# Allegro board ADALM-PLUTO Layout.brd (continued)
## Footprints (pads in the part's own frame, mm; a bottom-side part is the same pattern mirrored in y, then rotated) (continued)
L0805
  rect 1.194x1.448 smd: 1(-0.85,0) 2(0.85,0)
L0805-4PH39
  rect 0.889x0.406 smd: 1(-0.845,-0.403) 2(0.845,-0.403) 3(0.845,0.403) 4(-0.845,0.403)
L0805-F
  rect 1.092x1.499 smd: 1(-1.046,0) 2(1.046,0)
L2020_A
  custom 0.425x0.425 smd: 1(-1.606,-1.501) 2(1.606,-1.501) 3(1.606,1.501) 4(-1.606,1.501)
LED0804
  rect 0.787x0.762 smd: A(1.1,0) C(-1.1,0)
LSMSQ79H41
  rect 1.041x2.21 smd: 1(-0.724,0) 2(0.724,0)
LSMSQ157H83
  rect 1.473x3.683 smd: 1(-1.232,0) 2(1.232,0)
MSOP12
  rect 0.406x1.397 smd: 1(-1.625,-2.2) 2(-0.975,-2.2) 3(-0.325,-2.2) 4(0.325,-2.2) 5(0.975,-2.2) 6(1.625,-2.2) 7(1.625,2.2) 8(0.975,2.2) 9(0.325,2.2) 10(-0.325,2.2) 11(-0.975,2.2) 12(-1.625,2.2)
QFN16_4X4_PAD2_1X2_1
  oval 0.356x1.041 smd: 1(-0.975,-1.9) 2(-0.325,-1.9) 3(0.325,-1.9) 4(0.975,-1.9) 9(0.975,1.9) 10(0.325,1.9) 11(-0.325,1.9) 12(-0.975,1.9)
  oval 1.041x0.356 smd: 5(1.9,-0.975) 6(1.9,-0.325) 7(1.9,0.325) 8(1.9,0.975) 13(-1.9,0.975) 14(-1.9,0.325) 15(-1.9,-0.325) 16(-1.9,-0.975)
  rect 2.108x2.108 smd: PAD(0,0)
QFN16_4X4_PAD2_5X2_5
  oval 0.356x0.991 smd: 1(-0.975,-1.974) 2(-0.325,-1.974) 3(0.325,-1.974) 4(0.975,-1.974) 9(0.975,1.974) 10(0.325,1.974) 11(-0.325,1.974) 12(-0.975,1.974)
  oval 0.991x0.356 smd: 5(1.974,-0.975) 6(1.974,-0.325) 7(1.974,0.325) 8(1.974,0.975) 13(-1.974,0.975) 14(-1.974,0.325) 15(-1.974,-0.325) 16(-1.974,-0.975)
  rect 2.489x2.489 smd: PAD(0,0)
QFN32_5X5_PAD3_1X3_1
  oval 0.305x0.889 smd: 1(-1.75,-2.45) 2(-1.25,-2.45) 3(-0.75,-2.45) 4(-0.25,-2.45) 5(0.25,-2.45) 6(0.75,-2.45) 7(1.25,-2.45) 8(1.75,-2.45) 17(1.75,2.45) 18(1.25,2.45) 19(0.75,2.45) 20(0.25,2.45) 21(-0.25,2.45) 22(-0.75,2.45) 23(-1.25,2.45) 24(-1.75,2.45)
  oval 0.889x0.305 smd: 9(2.45,-1.75) 10(2.45,-1.25) 11(2.45,-0.75) 12(2.45,-0.25) 13(2.45,0.25) 14(2.45,0.75) 15(2.45,1.25) 16(2.45,1.75) 25(-2.45,1.75) 26(-2.45,1.25) 27(-2.45,0.75) 28(-2.45,0.25) 29(-2.45,-0.25) 30(-2.45,-0.75) 31(-2.45,-1.25) 32(-2.45,-1.75)
  rect 3.099x3.099 smd: PAD(0,0)
QFN32_5X5_PAD3_3X3_3
  oval 0.305x0.889 smd: 1(-1.75,-2.45) 2(-1.25,-2.45) 3(-0.75,-2.45) 4(-0.25,-2.45) 5(0.25,-2.45) 6(0.75,-2.45) 7(1.25,-2.45) 8(1.75,-2.45) 17(1.75,2.45) 18(1.25,2.45) 19(0.75,2.45) 20(0.25,2.45) 21(-0.25,2.45) 22(-0.75,2.45) 23(-1.25,2.45) 24(-1.75,2.45)
  oval 0.889x0.305 smd: 9(2.45,-1.75) 10(2.45,-1.25) 11(2.45,-0.75) 12(2.45,-0.25) 13(2.45,0.25) 14(2.45,0.75) 15(2.45,1.25) 16(2.45,1.75) 25(-2.45,1.75) 26(-2.45,1.25) 27(-2.45,0.75) 28(-2.45,0.25) 29(-2.45,-0.25) 30(-2.45,-0.75) 31(-2.45,-1.25) 32(-2.45,-1.75)
  rect 3.302x3.302 smd: PAD(0,0)
R0201
  rect 0.305x0.406 smd: 1(-0.318,0) 2(0.318,0)
R0402
  rect 0.61x0.61 smd: 1(-0.495,0) 2(0.495,0)
R0603
  rect 0.889x0.813 smd: 1(-0.737,0) 2(0.737,0)
R0603#2
  rect 0.711x0.914 smd: 1(-0.6,0) 2(0.6,0)
R0603H18
  rect 0.94x0.991 smd: 1(-0.787,0) 2(0.787,0)
R0805
  rect 0.838x1.295 smd: 1(-0.85,0) 2(0.85,0)
SON10_2X2_PAD1_5X0_9
  oval 0.203x0.762 smd: 1(-0.8,-1) 2(-0.4,-1) 3(0,-1) 4(0.4,-1) 5(0.8,-1) 6(0.8,1) 7(0.4,1) 8(0,1) 9(-0.4,1) 10(-0.8,1)
  rect 1.499x0.889 smd: PAD(0,0)
SOT23
  rect 1.016x1.397 smd: 1(-0.94,-1.118) 2(0.94,-1.118) 3(0,1.118)
SOT353
  rect 0.33x0.94 smd: 1(-0.65,-0.89) 2(0,-0.89) 3(0.65,-0.89) 4(0.65,0.89) 5(-0.65,0.89)
SOT-563
  rect 0.305x0.508 smd: 1(-0.508,-0.699) 2(0,-0.699) 3(0.508,-0.699) 4(0.508,0.699) 5(0,0.699) 6(-0.508,0.699)
SWSML140W138H55
  round 0.889 hole 0.711 unplated: (-0.9,0) (0.9,0)
  rect 1.041x1.397 smd: 1(-0.721,-1.799) 2(-0.721,1.799) 3(0.721,-1.799) 4(0.721,1.799)
  rect 0.508x1.092 smd: 5(-1.704,0)
TBGA24
  round 0.33 smd: A2(-2,-1) A3(-2,0) A4(-2,1) A5(-2,2) B1(-1,-2) B2(-1,-1) B3(-1,0) B4(-1,1) B5(-1,2) C1(0,-2) C2(0,-1) C3(0,0) C4(0,1) C5(0,2) D1(1,-2) D2(1,-1) D3(1,0) D4(1,1) D5(1,2) E1(2,-2) E2(2,-1) E3(2,0) E4(2,1) E5(2,2)
TPC75D45
  round 1.905 hole 1.143: 1(0,0)
TPSMC40
  round 1.016 hole 0.508: 1(0,0)
TSML150W160H160
  rect 0.762x1.651 smd: 1(-1.27,1.587) 2(0,1.587) 3(1.27,1.587) 4(1.27,-1.587) 5(0,-1.587) 6(-1.27,-1.587)
unnamed
  round 0.889 hole 0.635 unplated: (0,0)
unnamed#3
  round 1.651 hole 1.143: 1(0,0)
WLCSP4-2
  round 0.254 smd: A1(-0.25,-0.25) A2(-0.25,0.25) B1(0.25,-0.25) B2(0.25,0.25)
YSML98W79H35
  rect 1.092x0.991 smd: 1(-0.921,-0.72) 2(0.921,-0.72) 3(0.921,0.72) 4(-0.921,0.72)
YSML126W98H47
  rect 1.397x1.194 smd: 1(-1.2,-0.95) 2(1.2,-0.95) 3(1.2,0.95) 4(-1.2,0.95)

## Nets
1V8: C1.1 C10.1 C22.1 C25.1 C46.1 C48.1 C49.1 C50.1 C51.1 C52.1 C53.1 C65.1 C67.1 C69.1 C76.1 C77.1 C78.1 C82.1 C83.1 C90.1 C103.1 C104.1 C105.1 C106.1 C107.1 C108.1 C109.1 C110.1 C111.1 C112.1 C113.1 C114.1 C115.1 C116.1 C117.1 C118.1 C119.1 C120.1 C140.1 C149.1 C150.1 C152.1 C153.1 C154.1 C158.1 C159.1 C160.1 C161.1 C162.1 C163.2(N2) C168.1 C174.1 C186.1 C190.1 E1.1 E4.1 E5.1 L5.2(N2) P1.10(N5) R8.1 R11.1 R13.1 R14.1 R44.1 R45.1 R46.2(N2) R47.2(N2) R50.2(N2) R57.1 R64.2(N2) R68.1 R74.1 R76.1 R83.1 R84.2(N2) R94.1 R97.1 R107.1 R122.2(N2) U1.1 U1.2 U1.3 U1.15 U1.16 U4.A6 U4.B13 U4.C10 U4.D7 U4.E14 U4.F11 U4.G4 U4.H4 U4.H9 U4.H15 U4.J4 U4.J6 U4.J8 U4.J12 U4.K8 U4.K9 U4.L6 U4.M13 U4.N10 U4.P7 U4.R14 U7.1 U7.2 U7.3 U7.15 U7.16 U9.1(VCCIO) U10.5 U13.B4 U15.8 U15.11 U15.14 U15.28 U15.30 U15.32 UNK1V8.1 UNK1V8#2.1 Y1.4(VDD) Y2.4(VDD)
1V35: C54.1 C55.1 C56.1 C57.1 C58.1 C59.1 C60.1 C61.1 C86.1 C87.1 C88.1 C89.1 C91.1 C92.1 C94.1 C95.1 C96.1 C97.1 C100.1 C145.1 C148.1 C151.1 L2.2(N2) R41.2(N2) R62.1 U2.A1 U2.A8 U2.B2 U2.C1 U2.C9 U2.D2 U2.D9 U2.E9 U2.F1 U2.G7 U2.H2 U2.H9 U2.K2 U2.K8 U2.N1 U2.N9 U2.R1 U2.R9 U4.B3 U4.E4 U4.F1 U4.J2 U4.M3 U4.R4 U14.1 UNK1V35.1
GND: C1.2(N2) C2.2(N2) C3.2(N2) C4.2(N2) C5.2(N2) C6.2(N2) C7.1 C8.2(N2) C9.2(N2) C10.2(N2) C11.2(N2) C12.2(N2) C13.2(N2) C14.2(N2) C15.2(N2) C16.2(N2) C17.2(N2) C18.2(N2) C19.2(N2) C20.2(N2) C21.2(N2) C22.2(N2) C23.2(N2) C24.2(N2) C25.2(N2) C26.2(N2) C27.2(N2) C28.2(N2) C29.2(N2) C30.2(N2) C31.2(N2) C32.2(N2) C33.2(N2) C34.2(N2) C35.2(N2) C36.2(N2) C37.2(N2) C38.2(N2) C39.2(N2) C40.2(N2) C41.2(N2) C42.2(N2) C43.2(N2) C44.2(N2) C45.2(N2) C46.2(N2) C47.2(N2) C48.2(N2) C49.2(N2) C50.2(N2) C51.2(N2) C52.2(N2) C53.2(N2) C54.2(N2) C55.2(N2) C56.2(N2) C57.2(N2) C58.2(N2) C59.2(N2) C60.2(N2) C61.2(N2) C62.1 C63.1 C64.2(N2) C65.2(N2) C66.2(N2) C67.2(N2) C68.2(N2) C69.2(N2) C70.2(N2) C71.2(N2) C72.2(N2) C73.2(N2) C74.2(N2) C75.2(N2) C76.2(N2) C77.2(N2) C78.2(N2) C79.2(N2) C80.2(N2) C81.2(N2) C82.2(N2) C83.2(N2) C84.2(N2) C85.2(N2) C86.2(N2) C87.2(N2) C88.2(N2) C89.2(N2) C90.2(N2) C91.2(N2) C92.2(N2) C94.2(N2) C95.2(N2) C96.2(N2) C97.2(N2) C99.1 C100.2(N2) C101.2(N2) C102.2(N2) C103.2(N2) C104.2(N2) C105.2(N2) C106.2(N2) C107.2(N2) C108.2(N2) C109.2(N2) C110.2(N2) C111.2(N2) C112.2(N2) C113.2(N2) C114.2(N2) C115.2(N2) C116.2(N2) C117.2(N2) C118.2(N2) C119.2(N2) C120.2(N2) C121.2(N2) C122.2(N2) C123.2(N2) C124.2(N2) C125.1 C126.1 C127.2(N2) C128.2(N2) C129.1 C135.2(N2) C136.2(N2) C137.2(N2) C138.2(N2) C139.1 C140.2(N2) C141.2(N2) C142.1 C143.1 C145.2(N2) C146.2(N2) C147.1 C148.2(N2) C149.2(N2) C150.2(N2) C151.2(N2) C152.2(N2) C153.2(N2) C154.2(N2) C155.2(N2) C158.2(N2) C159.2(N2) C160.2(N2) C161.2(N2) C162.2(N2) C163.1 C164.2(N2) C165.2(N2) C166.1 C167.2(N2) C168.2(N2) C169.2(N2) C170.2(N2) C171.2(N2) C172.2(N2) C173.2(N2) C174.2(N2) C177.1 C178.2(N2) C180.2(N2) C182.2(N2) C183.2(N2) C184.2(N2) C185.2(N2) C186.2(N2) C187.2(N2) C188.2(N2) C189.2(N2) C190.2(N2) C191.2(N2) C192.2(N2) C193.1 C194.1 C195.2(N2) C196.1 C197.1 C198.2(N2) C199.2(N2) C200.2(N2) C201.2(N2) C202.2(N2) C203.2(N2) C205.2(N2) C206.2(N2) C207.1 C208.2(N2) C209.2(N2) C210.2(N2) C211.2(N2) C212.2(N2) C213.2(N2) C215.2(N2) CLK_IN.2 CLK_IN.3(SH2) CLK_OUT.2 CLK_OUT.3(SH2) D1.2 D3.1 D4.1 D7.1 D8.1 D9.1 D10.1 E6.1 E10.1 GND.1 GND#2.1 GND#3.1 GND#4.1 L10.3 P1.7 P1.9 P2.5 Q1.2(S) Q2.2(S) Q3.2(S) Q4.2(S) R2.1 R3.1 R9.2(N2) R15.2(N2) R40.2(N2) R42.2(N2) R49.1 R53.1 R54.2(N2) R55.2(N2) R61.1 R63.2(N2) R65.1 R66.1 R69.1 R72.2(N2) R73.2(N2) R75.2(N2) R77.2(N2) R78.1 R90.2(N2) R91.2(N2) R92.2(N2) R93.2(N2) R99.2(N2) R103.2(N2) R104.1 R116.2(N2) R119.2(N2) R120.2(N2) R121.2(N2) R165.2(N2) RX1A.2 RX1A.3 RX1A.4 RX1A.5(SH4) RX2A.2 RX2A.3(SH2) S1.3 S1.4 T1.1 T1.2 T1.5 T2.1 T2.2 T2.5 T3.1 T3.2 T3.5 T5.1 T5.2 T5.5 TX1A.2 TX1A.3 TX1A.4 TX1A.5(SH4) TX2A.2 TX2A.3(SH2) U1.6 U1.PAD U2.A9 U2.B1 U2.B3 U2.B9 U2.D1 U2.D8 U2.E1 U2.E2 U2.E8 U2.F9 U2.G1 U2.G8 U2.G9 U2.J2 U2.J8 U2.M1 U2.M9 U2.P1 U2.P9 U2.T1 U2.T9 U3.5 U3.6 U3.7 U3.8 U3.PAD U4.A1 U4.A11 U4.B8 U4.C5 U4.C15 U4.D2 U4.D12 U4.E5 U4.E7 U4.E8 U4.E9 U4.F10 U4.G3 U4.G5 U4.G13 U4.H6 U4.H8 U4.H10 U4.J5 U4.J9 U4.K4 U4.K7 U4.K10 U4.K14 U4.L1 U4.L5 U4.L11 U4.M8 U4.N5 U4.N15 U4.P2 U4.P12 U4.R9 U5.A4 U5.A5 U5.A6 U5.A12 U5.B1 U5.B2 U5.B12 U5.C1 U5.C2 U5.C4 U5.C7 U5.C8 U5.C9 U5.C10 U5.C11 U5.C12 U5.D1 U5.D12 U5.E1 U5.F1 U5.F3 U5.F7 U5.F9 U5.F11 U5.G1 U5.G10 U5.G12 U5.H1 U5.H2 U5.H3 U5.H5 U5.H6 U5.H7 U5.H9 U5.H10 U5.J1 U5.J2 U5.K1 U5.K2 U5.K12 U5.L1 U5.L2 U5.L3 U5.L7 U5.L8 U5.L9 U5.L10 U5.L11 U5.L12 U5.M4 U5.M5 U5.M6 U6.1 U6.19 U6.20 U6.21 U6.22 U6.PAD U7.6 U7.PAD U8.PAD U9.3 U9.13 U9.PAD U10.3 U11.3 U11.PAD U12.3 U12.PAD U13.B3 U14.4 U14.8 U14.PAD U15.PAD U16.B2 U17.1 U17.5 U17.8 Y1.2 Y2.2 Y3.2
PGND: C181.1 C214.2(N2) D2.2 E10.2(N2) L10.4(N4) P3.5 R58.2(N2)
VCCPINT: C17.1 C19.1 C20.1 C21.1 C64.1 C66.1 C68.1 C70.1 C71.1 C72.1 C73.1 C74.1 C75.1 L4.2(N2) R7.2(N2) U4.E10 U4.F9 U4.G6 U4.G10 U4.H5 U4.J10 U4.K5 U4.L10 UNK1P0V.1
VCCPLL: C85.1 C178.1 E1.2(N2) U4.F5(VCCPLL)
VDD33_USB: C165.1 U15.20
VDD_INTERFACE: C32.1 C33.1 C38.1 C43.1 C44.1 C45.1 E4.2(N2) U5.H12
VDDA1P1_RX_VCO: C125.2(N2) R51.2(N2) U5.G2 U5.G3
VIN: C8.1 C9.1 C11.1 C62.2(N2) C123.1 C135.1 C136.1 C137.1 C138.1 C164.1 C169.1 C184.1 C185.1 C188.1 C215.1 DS1.A(P) DS2.A(P) E2.1 E7.1 R1.2(N2) R6.1 R56.1 R59.2(N2) R221.1 R222.1 U3.12 U3.13 U6.14 U6.15 U6.16(VIN6) U6.25 U6.26 U6.27 U6.28 U8.9 U8.10 U8.15 U8.16 U9.10 U14.10 U15.21
VIN_5V_USB_DATA: C183.1 C210.1 E3.1 F1.2(N2) R88.1 U8.7 U8.8
VIN_5V_USB_POWER: C182.1 C209.1 C212.1 E9.1 R70.1 R80.1 U8.1 U8.2 U16.A1
1P3_SUPPLY_A: C14.1 C15.1 C16.1 C18.1 C23.1 C24.1 C28.1 C29.1 C34.1 C35.1 C39.1 C40.1 U5.B9 U5.B10 U5.E2 U5.F2 U5.J3 U5.K3 U7.9 U7.10 U7.11 U7.12 U7.13 U7.14(VOUT5) UNK1P3V_A.1
1P3_SUPPLY_B: C3.1 C4.1 C5.1 C6.1 C26.1 C27.1 C30.1 C31.1 C36.1 C37.1 C41.1 C42.1 C129.2(N2) C155.1 C166.2(N2) C167.1 C191.1 C192.1 C193.2(N2) C194.2(N2) L1.1 L7.1 L8.1 L9.1 U1.9 U1.10 U1.11 U1.12 U1.13 U1.14(VOUT5) U5.A9 U5.A10 U5.D2 U5.D3 U5.E3 U5.F12 U5.K4 U5.M9 U5.M10 UNK1P3V_B.1
1P8V_CLK: C121.1 C122.1 C170.1 R101.1 U12.1(VOUT) UNK1P8V_CLK.1 Y3.4(VDD)
3P3V: C198.1 C199.1 C203.1 E8.1 U5.B8 U11.1(VOUT) VDD_GPO.1(N1)
3P3V_CLK: C200.1 C201.1 C202.1 E8.2(N2) R85.1 U17.2 U17.6 U17.11(VDD)
AD9363_AUXADC: ADC.1(N1) C207.2(N2) U5.L5
AD9363_AUXDAC1: C206.1 DAC1.1(N1) R5.1 U5.B3
AD9363_AUXDAC2: C208.1 DAC2.1(N1) U5.C3
AD9363_GPO_0: GPO0.1(N1) U5.B7
AD9363_GPO_1: GPO1.1(N1) U5.B6
AD9363_GPO_2: GPO2.1(N1) U5.B5
AD9363_GPO_3: GPO3.1(N1) U5.B4
ADP2114_VIN: C141.1 R56.2(N2) U6.4 U6.8 U6.10 U6.31
CLK_SOURCE_SEL: Q2.1 Q3.1 R102.1 R103.1
COMP_1P8V: C142.2(N2) R60.1 U6.2
COMP_1P35V: C143.2(N2) C144.1 U6.7
CTRL_IN0: U4.F13 U5.C5
CTRL_IN1: U4.F14 U5.C6
CTRL_IN2: U4.G15 U5.D6
CTRL_IN3: U4.F15 U5.D5
DDR3_A0: R16.1 U2.N3 U4.P1
DDR3_A1: R22.1 U2.P7 U4.N1
DDR3_A2: R17.1 U2.P3 U4.M1
DDR3_A3: R23.1 U2.N2 U4.M4
DDR3_A4: R18.1 U2.P8 U4.P3
DDR3_A5: R24.1 U2.P2 U4.P4
DDR3_A6: R19.1 U2.R8 U4.P5
DDR3_A7: R25.1 U2.R2 U4.M5
DDR3_A8: R20.1 U2.T8 U4.P6
DDR3_A9: R26.1 U2.R3 U4.N4
DDR3_A10: R21.1 U2.L7 U4.J1
DDR3_A11: R27.1 U2.R7 U4.L2
DDR3_A12: R28.1 U2.N7 U4.M2
DDR3_A13: R34.1 U2.T3 U4.K2
DDR3_A14: R29.1 U2.T7 U4.K1
DDR3_BA0: R35.1 U2.M2 U4.M6
DDR3_BA1: R30.1 U2.N8 U4.R1
DDR3_BA2: R36.1 U2.M3 U4.N6
DDR3_CAS#: R32.1 U2.K3 U4.R5
DDR3_CK_N: R142.2(N2) U2.K7 U4.N2
DDR3_CK_P: R142.1 U2.J7 U4.N3
DDR3_CKE: R38.1 U2.K9 U4.L3
DDR3_CS#: R39.1 U2.L2 U4.R2
DDR3_DM0: U2.E7 U4.B1
DDR3_DM1: U2.D3 U4.D3
DDR3_DQ0: U2.E3 U4.D4
DDR3_DQ1: U2.F7 U4.A2
DDR3_DQ2: U2.F2 U4.C4
DDR3_DQ3: U2.F8 U4.C1
DDR3_DQ4: U2.H3 U4.B4
DDR3_DQ5: U2.H8 U4.A4
DDR3_DQ6: U2.G2 U4.C3
DDR3_DQ7: U2.H7 U4.A3
DDR3_DQ8: U2.D7 U4.E1
DDR3_DQ9: U2.C3 U4.D1
DDR3_DQ10: U2.C8 U4.E2
DDR3_DQ11: U2.C2 U4.E3
DDR3_DQ12: U2.A7 U4.F3
DDR3_DQ13: U2.A2 U4.G1
DDR3_DQ14: U2.B8 U4.H1
DDR3_DQ15: U2.A3 U4.H2
DDR3_DQS0_N: U2.G3 U4.B2
DDR3_DQS0_P: U2.F3 U4.C2
DDR3_DQS1_N: U2.B7 U4.F2
DDR3_DQS1_P: U2.C7 U4.G2
DDR3_ODT: R33.1 U2.K1 U4.K3
DDR3_RAS#: R37.1 U2.J3 U4.R6
DDR3_RST#: R42.1 U2.T2 U4.L4
DDR3_WE#: R31.1 U2.L3 U4.R3
EN_DAT_USB: R71.2(N2) R72.1 U8.6
EN_POW_USB: R70.2(N2) R71.1 U8.3
FB0: R2.2(N2) R4.1 U3.4
FB_1P8V: R64.1 R65.2(N2) U6.32
FB_1P35V: R62.2(N2) R63.1 U6.9
IO_02_34_AD9361_CLKOUT: AD9361_CLKOUT.1(N1) U4.P8 U5.J6
IO_02_34_AD9361_RST: U4.P9 U5.K5
IO_L01_34_FB_CLK: U4.P10 U5.F10
IO_L01_34_RX_D0: U4.H14 U5.K11
IO_L01_34_RX_D1: U4.J13 U5.J12
IO_L02_34_RX_D2: U4.G14 U5.K10
IO_L02_34_RX_D3: U4.H13 U5.J11
IO_L03_34_RX_D4: U4.G12 U5.K9
IO_L03_34_RX_D5: U4.H12 U5.J10
IO_L04_34_RX_D6: U4.G11 U5.K8
IO_L04_34_RX_D7: U4.J14 U5.J9
IO_L05_34_RX_D8: U4.J15 U5.K7
IO_L05_34_RX_D9: U4.K15 U5.J8
IO_L06_34_RX_D10: U4.H11 U5.J7
IO_L06_34_RX_D11: U4.J11 U5.H8
IO_L07_34_RX_FRAME: U4.N13 U5.G8
IO_L08_34_CTRL_OUT0: U4.L15 U5.D4
IO_L08_34_CTRL_OUT1: U4.M15 U5.E4
IO_L09_34_TX_FRAME: U4.L14 U5.G9
IO_L10_34_EN_AGC: U4.L13 U5.G5
IO_L11_34_ENABLE: U4.K12 U5.G6
IO_L11_34_TXNRX: U4.K11 U5.H4
IO_L12_MRCC_34_DATA_CLK: U4.L12 U5.G11
IO_L13_34_CTRL_OUT2: U4.N11 U5.E5
IO_L13_34_CTRL_OUT3: U4.N12 U5.E6
IO_L15_34_TX_D0: U4.P15 U5.E12
IO_L15_34_TX_D1: U4.R13 U5.D11
IO_L16_34_TX_D2: U4.R15 U5.E11
IO_L16_34_TX_D3: U4.P11 U5.D10
IO_L17_34_TX_D4: U4.R11 U5.E10
IO_L17_34_TX_D5: U4.R12 U5.D9
IO_L18_34_TX_D6: U4.P14 U5.E9
IO_L18_34_TX_D7: U4.P13 U5.D8
IO_L19_34_TX_D8: U4.N9 U5.E8
IO_L19_34_TX_D9: U4.M9 U5.D7
IO_L20_34_TX_D10: U4.R8 U5.F8
IO_L20_34_TX_D11: U4.R7 U5.E7
IO_L21_34_CTRL_OUT4: U4.M10 U5.F6
IO_L21_34_CTRL_OUT5: U4.M11 U5.F5
IO_L22_34_CTRL_OUT6: U4.N7 U5.F4
IO_L22_34_CTRL_OUT7: U4.N8 U5.G4
IO_L23_35_SPI_CLK: U4.E11 U5.J5
IO_L23_35_SPI_ENB: U4.E12 U5.K6
IO_L24_35_SPI_DI: U4.E13 U5.J4
IO_L24_35_SPI_DO: U4.F12 U5.L6
JTAG_TCK: P1.4 TCK.1(N1) U4.G9
JTAG_TDI: P1.8 TDI.1(N1) U4.L7
JTAG_TDO: P1.6 TDO.1(N1) U4.L8
JTAG_TMS: P1.2 TMS.1(N1) U4.L9
PG_1P0V: R6.2(N2) U3.16
PG_1P3V: C47.1 PG_1P3V.1(N1) R13.2(N2) R15.1 U1.5 U4.C9 U7.5 U11.4 U12.4
PG_1P8V: R59.1 U6.13 U6.29
PG_1P35V: R50.1 U1.4 U6.12 U7.4
PL_GPIO0: L10P.1(N1) U4.K13
PL_GPIO1: L12N.1(N1) U4.M12
PL_GPIO2: L24N.1(N1) U4.R10
PL_GPIO3: L7N.1(N1) R97.2(N2) U4.N14
PL_GPIO4: L9N.1(N1) R68.2(N2) U4.M14
PS-SRST#: R74.2(N2) U4.B11 U13.A4
PS_GPIO0: MIO0.1(N1) U4.D8
PS_GPIO1: MIO10.1(N1) U4.B10
PS_GPIO2: MIO11.1(N1) U4.D6
PS_GPIO3: MIO09.1(N1) U4.B5
PS_GPIO4: MIO53.1(N1) U4.C13
PS_GPIO5: MIO49.1(N1) U4.D13
PS_GPIO6: MIO48.1(N1) R102.2(N2) U4.B12
PS_MIO01_500_QSPI0_SS_B: R14.2(N2) U4.A5 U13.C2
PS_MIO02_500_QSPI0_IO0: R120.1 U4.A8 U13.D3
PS_MIO03_500_QSPI0_IO1: R119.1 U4.A7 U13.D2
PS_MIO04_500_QSPI0_IO2: R121.1 U4.C8 U13.C4(W#DQ2)
PS_MIO05_500_QSPI0_IO3: JTAG_BOOT.1(N1) P1.5 R122.1 U4.A9 U13.D4
PS_MIO06_500_QSPI0_SCLK: R116.1 U4.A10 U13.B2
PS_MIO07_500_USB_RESET_B: R76.2(N2) U4.A12 U15.27
PS_MIO28_501_USB0_D4: U4.A15 U15.7
PS_MIO29_501_USB0_DIR: U4.D11 U15.31
PS_MIO30_501_USB0_STP: U4.B15 U15.29
PS_MIO31_501_USB0_NXT: U4.C12 U15.2
PS_MIO32_501_USB0_D0: U4.E15 U15.3
PS_MIO33_501_USB0_D1: U4.C11 U15.4
PS_MIO34_501_USB0_D2: U4.D15 U15.5
PS_MIO35_501_USB0_D3: U4.A14 U15.6
PS_MIO36_501_USB0_CLK: U4.B14 U15.1
PS_MIO37_501_USB0_D5: U4.C14 U15.9
PS_MIO38_501_USB0_D6: U4.A13 U15.10
PS_MIO39_501_USB0_D7: U4.D14 U15.13
PWR_CLK: R89.2(N2) R90.1 U3.1
RX1A_N: C133.2(N2) U5.M2
RX1A_P: C134.2(N2) U5.M1
RX2A_N: C175.2(N2) R69.2(N2) U5.A1
RX2A_P: C176.2(N2) R104.2(N2) U5.A2
SYNC: L4.1 U3.9 U3.10 U3.11
TX1A_N: C131.1 L8.2(N2) U5.M8
TX1A_P: C132.1 L9.2(N2) U5.M7
TX2A_N: C130.1 L1.2(N2) U5.A7
TX2A_P: C156.1 L7.2(N2) U5.A8
TX_VCO_1P1V_SUPPLY: C128.1 R52.1 U5.A11 U5.B11
UART_RX: P1.1 R95.2(N2) RX.1(N1) U4.C6
UART_TX: P1.3 TX.1(N1) U4.B7 U9.2
UNNAMED_2_ADM7160V2_I254_VIN: C173.1 E2.2(N2) U12.6
UNNAMED_2_ADM7160V2_I348_VIN: C195.1 E7.2(N2) U11.6
UNNAMED_2_ADP1754_I93_SS: C2.1 U1.7
UNNAMED_2_ADP1754_I233_SS: C12.1 U7.7
UNNAMED_2_ADP2164_I29_EN: C13.1 R1.1 U3.3 U3.14(VIN) U3.15
UNNAMED_2_ADP2164_I29_RT: R3.2(N2) U3.2
UNNAMED_2_RES_I251_N2: R4.2(N2) R7.1
UNNAMED_3_ICXC7Z010_I16_PSCLK50: R12.2(N2) U4.C7
UNNAMED_3_ICXC7Z010_I16_PSMIO75: R83.2(N2) U4.D9
UNNAMED_3_ICXC7Z010_I16_PSMIO85: R84.1 U4.B6
UNNAMED_3_RES_I2_N1: R8.2(N2) R9.1 Y2.1
UNNAMED_3_RES_I48_N1: R12.1 Y2.3
UNNAMED_4_ICMT41K256M16_I98_ZQ: R165.1 U2.L8(ZQ)
UNNAMED_4_ICTPS51206_I44_S3: R222.2(N2) U14.7
UNNAMED_4_ICTPS51206_I44_S5: R221.2(N2) U14.9
UNNAMED_4_ICTPS51206_I44_VLDOIN: R44.2(N2) U14.2
UNNAMED_4_ICTPS51206_I44_VTTSNS: C80.1 R43.2(N2) U14.5(VTTSNS)
UNNAMED_4_ICXC7Z010_I26_PSDDR_1: R40.1 U4.H3
UNNAMED_4_ICXC7Z010_I26_PSDDRVR: R41.1 U4.J3
UNNAMED_5_CAP_I83_N1: C93.1 C98.1 E5.2(N2) U4.F7
UNNAMED_5_CAP_I83_N2: C93.2(N2) C98.2(N2) E6.2(N2) U4.F6 U4.F8 U4.G8 U4.H7 U4.J7
UNNAMED_5_DIOLED_I62_N: DS2.C R87.1
UNNAMED_5_DIOLED_I91_N: DS1.C R48.1
UNNAMED_5_ICXC7Z010_I93_DONE0: Q1.1 U4.M7
UNNAMED_5_ICXC7Z010_I93_INITB0: R47.1 U4.D5
UNNAMED_5_ICXC7Z010_I93_PROGRAM: R46.1 U4.K6
UNNAMED_5_ICXC7Z010_I93_VCCBATT: R45.2(N2) U4.E6
UNNAMED_5_ICXC7Z010_I93_VP0: R11.2(N2) R66.2(N2) R91.1 U4.G7
UNNAMED_5_RES_I63_N2: Q4.3 R87.2(N2)
UNNAMED_5_RES_I90_N2: Q1.3 R48.2(N2)
UNNAMED_7_AD9363_I87_RBIAS: R49.2(N2) U5.L4
UNNAMED_7_AD9363_I87_XTALN: C124.1 C157.2(N2) C204.2(N2) U5.M12(XTALN)
UNNAMED_7_CAP_I14_N1: C157.1 R86.2(N2) R99.1
UNNAMED_7_CAP_I22_N2: C126.2(N2) R51.1
UNNAMED_7_CAP_I25_N1: C127.1 R52.2(N2)
UNNAMED_7_CAP_I57_N2: C132.2(N2) T5.4
UNNAMED_7_CAP_I58_N2: C131.2(N2) T5.6(SEC_DOT)
UNNAMED_7_CAP_I85_N1: C134.1 T1.4
UNNAMED_7_CAP_I86_N1: C133.1 T1.6(SEC_DOT)
UNNAMED_7_CAP_I92_N1: C179.1 CLK_IN.1 D7.2(N2)
UNNAMED_7_CAP_I92_N2: C179.2(N2) R10.1 R96.1
UNNAMED_7_CAP_I93_N1: C180.1 R96.2(N2) U17.4
UNNAMED_7_CAP_I116_N1: C175.1 T2.6(SEC_DOT)
UNNAMED_7_CAP_I117_N1: C176.1 T2.4
UNNAMED_7_CAP_I118_N2: C130.2(N2) T3.6(SEC_DOT)
UNNAMED_7_CAP_I119_N2: C156.2(N2) T3.4
UNNAMED_7_CAP_I147_N1: C205.1 R100.1
UNNAMED_7_CAP_I149_N1: C204.1 Y3.3
UNNAMED_7_CNBNC3P_I43_CNTR: D3.2(N2) RX2A.1 T2.3
UNNAMED_7_CNBNC3P_I74_CNTR: D10.2(N2) T3.3 TX2A.1
UNNAMED_7_CNBNC3P_I125_CNTR: CLK_OUT.1 D8.2(N2) R98.2(N2) R100.2(N2)
UNNAMED_7_CNBNC5P_I64_CNTR: D4.2(N2) RX1A.1 T1.3
UNNAMED_7_CNBNC5P_I83_CNTR: D9.2(N2) T5.3 TX1A.1
UNNAMED_7_ICLTC6957V3_I120_IN: R10.2(N2) U17.3
UNNAMED_7_ICLTC6957V3_I120_OUT1: R86.1 U17.10
UNNAMED_7_ICLTC6957V3_I120_OUT2: R98.1 U17.9
UNNAMED_7_ICLTC6957V3_I120_SD1: Q3.3 R85.2(N2) U17.7 U17.12
UNNAMED_7_RES_I152_N1: R5.2(N2) R67.1 Y3.1
UNNAMED_7_RES_I152_N2: Q2.3 R67.2(N2) R101.2(N2)
UNNAMED_9_ADP198_I365_VOUT: C171.1 C172.1 F1.1 U16.A2(VOUT)
UNNAMED_9_ADP2114_I196_FREQ: R53.2(N2) U6.3
UNNAMED_9_ADP2114_I196_OPCFG: R54.1 U6.6
UNNAMED_9_ADP2114_I196_SS1: C7.2(N2) U6.30
UNNAMED_9_ADP2114_I196_SS2: C139.2(N2) U6.11
UNNAMED_9_ADP2114_I196_SW1: L3.1 R89.1 U6.23 U6.24
UNNAMED_9_ADP2114_I196_SW3: L2.1 U6.17 U6.18
UNNAMED_9_CAP_I163_N1: C146.1 L3.2(N2) L5.1
UNNAMED_9_CAP_I214_N2: C147.2(N2) R60.2(N2)
UNNAMED_9_CAP_I224_N2: C144.2(N2) R61.2(N2)
UNNAMED_9_CAP_I358_N2: C177.2(N2) P2.SH1 P2.SH2 P2.SH3(N8) R55.1
UNNAMED_9_CAP_I377_N2: C181.2(N2) P3.SH1 P3.SH2 P3.SH3(N8) R58.1
UNNAMED_9_CAP_I446_N1: C214.1 D2.5(VCC) E11.2(N2) L10.1 P3.1
UNNAMED_9_CAP_I447_N1: C213.1 E9.2(N2) E11.1 L10.2
UNNAMED_9_CHOKE4P_I350_N2: D1.1 L6.2 P2.3
UNNAMED_9_CHOKE4P_I350_N3: D1.6 L6.3 P2.2
UNNAMED_9_CN5P3SHLD_I359_N1: C211.1 D1.5(VCC) E3.2(N2) P2.1
UNNAMED_9_CN5P3SHLD_I378_N4: D2.3 P3.4
UNNAMED_9_LINLTC4415_I386_CLIM1: R78.2(N2) U8.4
UNNAMED_9_LINLTC4415_I386_CLIM2: R73.1 U8.5
UNNAMED_11_741G126_I97_Y: R94.2(N2) R95.1 U10.4(Y)
UNNAMED_11_CAP_I83_N1: C187.1 R80.2(N2) R92.1 U9.9
UNNAMED_11_CAP_I92_N1: C189.1 U9.8
UNNAMED_11_ICFT230XQ_I103_USBDM: R79.2(N2) U9.7
UNNAMED_11_ICFT230XQ_I103_USBDP: R81.2(N2) U9.6
UNNAMED_11_ICUSB3320C_I29_RBIAS: R77.1 U15.24
UNNAMED_11_ICUSB3320C_I29_REFCL: R82.1 U15.26
UNNAMED_11_RES_I67_N2: R82.2(N2) Y1.3
USB_FS_SLEEP: R93.1 U9.14 U10.1
USB_ID: D1.3 P2.4 U15.23
USB_OTG_CPEN: U15.17 U16.B1
USB_OTG_N: L6.4(N4) U15.19
USB_OTG_P: L6.1 U15.18
USB_UART_N: C196.2(N2) D2.6 P3.2 R79.1
USB_UART_P: C197.2(N2) D2.1 P3.3 R81.1
USB_UART_TX: R107.2(N2) U9.15 U10.2
USB_VBUS_OTG: R88.2(N2) U15.22
USR_BTN: R57.2(N2) S1.1 U4.B9
USR_LED: Q4.1 R75.1 U4.D10
VTT_0P75: C79.1 C101.1 R16.2(N2) R17.2(N2) R18.2(N2) R19.2(N2) R20.2(N2) R21.2(N2) R22.2(N2) R23.2(N2) R24.2(N2) R25.2(N2) R26.2(N2) R27.2(N2) R28.2(N2) R29.2(N2) R30.2(N2) R31.2(N2) R32.2(N2) R33.2(N2) R34.2(N2) R35.2(N2) R36.2(N2) R37.2(N2) R38.2(N2) R39.2(N2) R43.1 U14.3
VTTVREF: C63.2(N2) C81.1 C84.1 C99.2(N2) C102.1 U2.H1 U2.M8 U4.F4 U14.6

Pads without a net: D1 4; D2 4; S1 2 5; U1 8; U2 J1 J9 L1 L9 M7; U5 A3 G7 H11 M3 M11; U6 5; U7 8; U8 11 12 13 14; U9 4 5 11 12 16; U11 2 5; U12 2 5; U13 A2 A3 A5 B1 B5 C1 C3 C5 D1 D5 E1 E2 E3 E4 E5; U15 12 15 16 25; Y1 1

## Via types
v1: diameter 0.508, hole 0.254, TOP to BOTTOM, 883 vias
v2: diameter 0.406, hole 0.203, TOP to BOTTOM, 601 vias

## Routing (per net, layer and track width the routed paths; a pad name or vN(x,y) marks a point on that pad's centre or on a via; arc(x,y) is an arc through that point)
1V8: length 140.5
  TOP w0.203: 41.57,9.21 41.69,9.09
  TOP w0.305: v1(74.27,29.16) 74.8,28.62 U15.32 ; v1(67.54,38.43) 66.64,38.43 R84.2 ; U4.J6 v2(53.13,35.35) ; v1(77.44,22.3) 77.3,22.44 U15.14 ; U4.K8 v2(52.33,33.75) ; U4.J4 v2(53.13,36.95) ; 99.54,8.46 98.4,8.46 v1(98.02,8.07) ; 99.54,8.46 99.79,8.2 R68.1 ; 99.54,8.46 99.79,8.71 R97.1 ; U4.D7 v2(57.93,34.55) ; UNK1V8#2.1 81.51,33.35 ; UNK1V8#2.1 81.51,31.82 ; UNK1V8#2.1 82.27,32.59 ; 40.92,9.21 U7.2 ; U7.2 U7.1 ; U7.2 U7.3 41.57,9.21 ; U4.N10 v2(49.93,31.35) ; U4.H15 v2(54.33,27.15) ; U7.1 40.27,9.21 ; U7.1 39.84,9.98 ; R47.2 v1(65.12,39.23) ; C25.1 31.94,12.27 ; C25.1 31.53,12.72 ; C25.1 31.53,11.81 ; U4.B13 v2(59.53,28.95) ; Y2.4 70.4,34.62 C46.1 71.54,35.19 v1(71.47,35.25) ; U13.B4 v2(73.61,45.31) ; U15.30 75.8,29.27 v1(75.79,29.28) ; U15.11 v1(75.8,22.31) ; U4.F11 v2(56.33,30.55) ; R74.1 65.25,29.78 v1(65.25,29.54) ; U4.A6 v2(60.43,34.95) ; U4.J8 v2(53.13,33.75) ; v1(76.81,29.28) 76.8,29.28 U15.28 ; U4.P7 v2(49.13,34.55) ; 41.16,8.46 C10.1 ; C10.1 41.57,8 ; C10.1 41.57,8.91 ; 38.57,10.91 U7.16 ; U7.16 39.35,10.48 ; U7.16 U7.15 ; R8.1 v1(72.6,36.9) ; U4.E14 v2(57.13,28.15) ; Y1.4 78.4,34.54 C163.2 v1(78.97,35.89) ; U4.C10 v2(58.73,31.35) ; U4.K9 v2(52.33,32.95) ; U15.8 v1(74.1,23.44) ; U4.G4 v2(55.53,36.95) ; U4.R14 v2(48.33,28.15) ; U4.J12 v2(53.13,29.75) ; U4.H9 v2(53.93,32.95) ; U4.H4 v2(54.73,36.95) ; U4.L6 v2(52.33,34.55) ; U4.M13 v2(50.73,28.95)
  TOP w0.508: 39.08,54.63 R44.1 ; R44.1 39.63,54.07 ; R44.1 39.63,55.19
  TOP w0.635: 32.42,9.66 C22.1 ; C22.1 33.06,10.36 ; C22.1 32.42,11.06 ; E4.1 34.23,12.3 ; E4.1 33.25,11.45 ; E4.1 32.27,12.3
  TOP w0.762: 37.25,54.62 C83.1 ; C83.1 38.1,55.42 ; C83.1 38.95,54.62 ; 35.16,54.62 C82.1 ; C82.1 36.02,55.42 ; C82.1 36.87,54.62
  TOP w1.016: 81.76,35.15 L5.2 83.12,35.93
  TOP w1.27: 83.75,31.44 C149.1 84.81,32.7 ; 84.81,33.23 C150.1 ; C150.1 84.81,35.75 ; C150.1 83.75,34.49
  BOTTOM w0.203: 82.92,34.88 v1(82.9,34.87)
  BOTTOM w0.254: R94.1 60.59,64.53 C190.1 61.07,63.91 U10.5 61.18,63.17 R107.1 ; C186.1 65.16,64.87 U9.1
  BOTTOM w0.305: C107.1 v2(59.83,25.64) C113.1 ; U1.2 27.67,55.26 ; U1.16 25.97,56.84 U1.15 25.32,57.3 25.75,57.73 ; U1.16 25.97,57.61 ; U1.16 26.4,56.83 ; C140.1 v1(76.81,29.28) C168.1 ; R13.1 73.16,32.79 v1(73.16,33.6) ; R76.1 59.64,28.35 C111.1 ; C118.1 50.63,28.85 v2(50.73,28.95) 50.82,29.04 C110.1 ; v2(57.13,28.15) 56.91,28.36 C161.1 ; v2(54.33,27.15) 54.35,27.16 C119.1 ; R50.2 v1(80.36,45.03) ; R83.1 64.14,32.75 v1(64.23,32.84) ; v2(57.14,25.64) 56.96,25.46 C117.1 ; v1(75.79,29.28) C154.1 ; C69.1 59.34,31.65 59.03,31.65 v2(58.73,31.35) 59.23,30.85 C162.1 ; C90.1 v2(46.62,32.56) C78.1 ; v2(73.61,45.31) 73.23,45.69 C48.1 ; v1(78.97,35.89) 79.81,35.89 R57.1 ; 26.89,56.34 U1.1 27.67,55.91 ; 26.01,58.02 26.01,58.43 26.46,58.43 ; C108.1 v2(46.62,30.94) ; R45.1 60.93,33.65 60.61,33.97 C53.1 60.43,34.63 v2(60.43,34.95) 60.43,35.27 C52.1 ; v1(62.71,64.34) 61.89,64.34 C190.1 ; C186.1 v1(65.06,65.61) ; C120.1 49.13,33.85 ; R14.1 v1(75.54,47.57) ; U1.3 27.66,54.61 ; R64.2 84.68,35.25
  BOTTOM w0.406: C67.1 v2(51.93,25.64) C106.1 ; C50.1 62.04,30.95 v2(62.03,30.95) 62.04,30.94 C159.1 v2(62.04,29.75) C160.1 62.04,28.45 v2(62.03,28.45) 62.03,27.8 C103.1 62.83,27.8 v2(62.83,28.45) ; 49.13,33.85 49.13,33.85 v2(49.13,34.55) 48.61,34.55 48.29,34.24 C51.1 ; C115.1 v2(57.14,25.64) ; R46.2 50.63,32.05 v2(49.93,31.35) 49.32,31.35 C116.1 ; v2(59.53,28.95) 59.53,28.95 C111.1 ; C109.1 v2(54.34,25.64) C105.1 ; 43.53,32.95 43.53,31.45 43.57,31.42 C77.1 43.53,31.33 43.53,29.79 43.99,29.33 v2(44.04,29.33) ; C114.1 48.33,27.64 v2(48.33,28.15) 48.33,28.65 C112.1
  BOTTOM w0.508: 43.53,32.95 43.53,33.22 v1(44.3,33.98) 44.04,34.24 44.04,35.73 C76.1 v1(44.02,37.16) ; v1(70.58,42.75) R122.2 ; R11.1 65.92,39.23 v1(65.12,39.23) ; v2(47.34,24.73) 48.31,24.73 C65.1 48.68,24.71 v2(49.63,24.71) ; v2(44.42,24.71) 45.38,24.71 C104.1 45.74,24.73 v2(46.71,24.73) ; v1(68.3,44.9) 67.6,44.9 E5.1 67.52,43.89 v1(68.3,43.89)
  BOTTOM w0.635: 84.87,33.41 C152.1 ; C152.1 84.24,34.11 ; C152.1 84.87,34.81 ; C153.1 84.87,33.28 ; C153.1 84.87,31.89 ; C153.1 84.24,32.59 ; E1.1 69.99,36.23 69.59,36.63 C174.1 69.59,38.15 v1(69.38,38.36)
  BOTTOM w0.762: 65.25,29.14 C158.1 64.2,27.89 ; C49.1 65.25,32.57 ; C49.1 65.25,30.06 ; C49.1 64.2,31.32
  vias: v1(28.09,55.93) v1(28.09,55.31) v1(28.09,54.63) v1(28.75,55.93) v1(28.75,55.29) v1(28.8,54.63) v1(29.4,55.93) v1(29.41,55.29) v1(29.44,54.63) v1(33.5,11) v1(33.5,10.36) v1(33.5,9.73) v1(34.14,11) v1(34.14,10.36) v1(34.14,9.73) v1(35.15,56.21) v1(36.04,56.21) v1(37.06,56.21) v1(38.07,56.21) v1(40.23,8.33) v1(40.23,7.69) v1(40.23,7.06) v1(40.87,8.33) v1(40.87,7.69) v1(40.87,7.06) v1(41.5,7.69) v1(41.5,7.06) v1(64.49,29.54) v1(64.88,32.84) v1(65.52,32.84) v1(65.89,29.54) v1(82.9,34.11) v1(82.9,33.35) v1(82.9,32.59) v1(82.9,31.82) v1(82.9,31.06) v1(83.54,34.87) v1(83.54,34.11) v1(83.54,33.35) v1(83.54,32.59) v1(83.54,31.82) v1(83.54,31.06)
1V35: length 42.3
  TOP w0.203: U14.1 40.8,56.08 40.68,55.95 v1(40.44,55.95)
  TOP w0.305: U2.R9 v2(50.42,49.47) ; 81.63,55.45 UNK1V35.1 80.87,54.68 ; v2(52.02,49.47) 51.62,49.07 U2.N9 ; U4.E4 v2(57.13,36.95) ; U2.K8 v2(53.62,49.47) ; U2.D9 v2(58.42,48.67) ; v2(55.53,39.35) 55.53,39.35 U4.F1 ; U2.N1 v2(51.22,55.87) ; U2.F1 v2(57.62,55.87) ; U2.K2 v2(53.62,55.07) ; U2.D2 v2(59.22,55.07) ; U2.R1 v2(49.62,55.87) ; U4.B3 v2(59.53,37.75) ; U2.B2 v2(60.82,55.07) ; U4.R4 v2(48.23,36.55) ; U2.G7 v2(56.82,51.07) ; U2.C1 v2(60.02,55.87) ; U2.E9 v2(57.62,48.67) ; U4.J2 v2(53.13,38.55) ; U4.M3 v2(50.73,37.75) ; U2.A8 v2(61.62,49.47) ; U2.C9 v2(60.02,48.67) ; v2(63.14,38.16) 63.22,38.07 C60.1 ; U2.H9 v2(55.22,48.67) ; U2.A1 v2(61.62,55.87) ; U2.H2 v2(56.02,55.07)
  TOP w0.406: v2(53.53,42.15) 54.03,42.15 C57.1 ; v2(51.73,42.15) 52.23,42.15 C58.1 ; C56.1 v1(45.82,35.27)
  TOP w0.635: 83.63,54.44 C151.1 82.99,55.14
  TOP w1.016: C148.1 83.86,51.8 ; C148.1 83.86,49.69 ; C148.1 82.95,50.75 ; C145.1 83.86,54.21 ; C145.1 82.95,53.16 ; C145.1 83.86,52.11 ; 64.37,54.56 C100.1 ; C100.1 66.89,54.56 ; C100.1 65.63,53.5
  BOTTOM w0.203: R62.1 84.3,49.1 v1(83.92,49.48)
  BOTTOM w0.305: v2(53.62,55.07) 54.22,54.47 C89.1 ; v2(50.42,49.47) 50.11,49.47 C86.1 ; C88.1 61.62,56.47 v2(61.62,55.87) ; C91.1 55.3,48.75 v2(55.22,48.67) ; C94.1 59.84,56.05 v2(60.02,55.87) ; v2(53.13,38.55) 53.63,38.55 R41.2 ; UNK1V35.1 v1(82.01,55.45) ; C87.1 60.63,48.67 v2(60.02,48.67) ; v2(56.82,51.07) 56.3,51.07 C92.1 ; C97.1 61.7,49.39 v2(61.62,49.47) ; C96.1 49.53,55.95 v2(49.62,55.87) ; C95.1 57.71,55.96 v2(57.62,55.87) ; C61.1 47.52,36.34
  BOTTOM w0.406: v2(55.53,39.35) 55.53,39.35 55.53,39.76 C55.1 ; v2(48.23,36.55) 47.73,36.55 47.52,36.34 ; v2(53.13,38.55) 53.12,38.56 C59.1
  vias: v1(64.11,54.94) v1(64.11,53.92) v1(65.12,53.29) v1(66.14,53.29) v1(67.16,54.94) v1(67.16,54.05) v1(82.01,54.81) v1(82.01,54.18) v1(82.01,53.54) v1(82.01,52.91) v1(82.01,52.27) v1(82.65,55.45) v1(82.65,54.81) v1(82.65,54.18) v1(82.65,53.54) v1(82.65,52.91) v1(82.65,52.27) v2(56.11,43.57) v2(56.11,42.96)
GND: length 615.9
  TOP w0.152: U5.C7 32.34,32.08 v2(29.15,32.08) ; v2(26.75,32.08) 28.34,32.08 U5.H7
  TOP w0.203: U5.L8 26.13,31.09 26.13,31.47 U5.L7 ; 42.37,55.19 42,55.55 U14.4 42,57.08 U14.PAD U14.8
  TOP w0.254: 13.31,18.62 13.55,18.38 C200.2 12.72,17.93 ; 101.58,43.76 U16.B2 101.19,43.63
  TOP w0.305: U2.B3 v2(60.82,53.47) ; C177.1 106.91,43.19 ; C177.1 107.61,42.56 ; C177.1 106.21,42.56 ; U4.N15 v2(50.33,27.25) ; U4.D12 v2(57.93,29.75) ; 89.46,20.9 U3.6 ; 89.46,20.9 v2(89.78,20.57) 89.46,20.25 U3.7 ; 89.46,20.9 88.81,21.55 U3.5 ; U3.6 U3.5 ; U3.6 87.06,20.9 ; U3.6 U3.7 ; C10.2 v1(42.77,8.46) ; 45.27,60.37 C84.2 44.87,60.83 ; U4.J9 v2(53.13,32.95) ; 9.42,13 R99.2 8.86,13.54 ; Q1.2 103.31,18.69 ; Q1.2 104.27,17.93 ; Q1.2 103.31,17.17 ; Q1.2 102.36,17.93 ; U4.L5 v2(51.53,36.15) ; 16.59,10.84 U17.1 17.54,10.39 ; C56.2 45.07,36.82 ; C56.2 45.63,36.26 ; C56.2 44.51,36.26 ; U5.M4 v2(25.14,34.48) ; U5.A6 v2(34.85,32.48) ; U5.L2 v2(26.74,36.08) U5.K2 ; C46.2 72.58,34.62 ; C46.2 72.17,34.16 ; C46.2 72.17,35.19 v1(72.24,35.25) ; 42.7,34.15 C166.1 42.71,33.53 ; U4.K4 v2(52.33,36.95) ; U5.L8 v2(25.95,30.48) U5.L9 v2(25.95,29.68) U5.L10 v2(25.95,28.88) U5.L11 v2(25.95,28.08) U5.L12 v2(25.95,27.28) 25.95,26.5 ; GND#4.1 59.66,11.38 ; GND#4.1 59.66,9.85 ; GND#4.1 60.43,10.61 ; GND#4.1 58.9,10.61 ; U5.H7 v2(29.15,32.08) ; U4.P2 v2(49.13,38.55) ; U5.K1 v2(26.74,36.88) U5.L1 ; v2(53.93,33.75) 54.33,33.35 U4.H8 ; U5.H5 v2(28.35,33.68) ; 68.71,6.17 P1.9 67.92,5.38 ; Q4.2 104.27,11.26 ; Q4.2 102.36,11.26 ; Q4.2 103.31,12.02 ; Q4.2 103.31,10.5 ; 20.48,16.13 C180.2 20.48,15.21 ; C43.2 29.88,25.88 ; U5.F9 v2(30.74,29.68) ; v1(71.13,33.53) 70.8,33.86 v1(66.24,33.86) v1(65.14,33.86) 62.58,33.86 v1(62.33,34.11) ; U4.L1 v2(51.93,39.45) ; 48.82,56.16 v2(48.82,55.87) U2.T1 ; C169.2 49.91,13.16 ; C169.2 49.91,12.14 ; C169.2 49.38,12.65 ; C141.2 96.99,47.37 ; C141.2 96.99,46.25 ; C141.2 97.55,46.81 ; C146.2 86.47,38.64 ; C146.2 85.64,37.67 ; C146.2 86.47,36.69 ; Y1.2 77.1,33.35 ; Y1.2 76.35,32.55 ; Y1.2 77.1,31.75 ; C58.2 52.33,43.61 ; C58.2 52.89,43.05 ; C58.2 51.77,43.05 ; 96.11,41.95 R53.1 96.67,42.5 ; v1(16.38,12.87) 16.38,12.89 16.93,13.44 U17.5 ; U5.H6 v2(28.35,32.88) ; 46.58,14.05 C170.2 ; 10.65,15.93 C205.2 ; C205.2 10.25,16.38 ; C205.2 10.65,16.84 ; C60.2 63.86,38.07 v2(63.94,38.16) ; 18.61,15.64 C199.2 ; C199.2 18.1,16.17 ; C199.2 19.11,16.17 ; 44.68,11.16 C12.2 ; C12.2 44.05,11.57 v1(44.04,11.56) U7.6 41.57,11.56 v2(41.25,11.88) ; C12.2 45.13,11.57 ; C210.2 96.33,62.65 ; C210.2 95.48,63.45 ; C210.2 94.63,62.65 ; 91.62,15.5 C8.2 91.16,15.1 ; U5.E1 v2(30.74,36.88) U5.F1 ; 22.52,34.16 R49.1 ; R49.1 22.11,34.62 ; R49.1 22.52,35.08 ; 107.25,26.62 S1.4 ; S1.4 107.25,28.53 ; S1.4 108.03,27.58 ; U3.5 87.81,21.98 ; U3.5 87.06,21.55 ; 88.8,44.68 89.14,45.02 U6.19 ; R103.2 15.98,4.52 ; R103.2 15.44,3.96 ; R103.2 15.44,5.08 ; GND.1 34.26,66.3 ; GND.1 35.34,65.22 ; GND.1 34.26,64.14 ; GND.1 33.18,65.22 ; U5.H3 v2(28.35,35.28) ; C211.2 98.69,38.26 ; C211.2 98.69,36.56 ; C211.2 97.89,37.41 ; C182.2 105.57,43.95 ; C182.2 106.21,43.25 ; C182.2 105.57,42.55 ; U5.L7 v2(26.75,32.08) ; v2(29.65,27.15) 29.62,27.17 29.6,27.17 ; U2.B1 v2(60.82,55.87) ; v2(33.14,27.28) U5.C12 v2(33.14,28.08) U5.C11 v2(33.14,28.88) U5.C10 v2(33.14,29.68) U5.C9 v2(33.14,30.48) U5.C8 v2(33.14,31.28) U5.C7 ; C45.2 27.85,25.52 ; C45.2 27.85,24.41 ; C45.2 27.29,24.97 ; U4.N5 v2(49.93,36.15) ; 77.76,36.35 C163.1 v1(77.23,35.89) ; U6.1 94.81,42.52 v1(95.35,41.98) ; R9.2 72.06,37.73 ; R9.2 71.6,38.14 ; R9.2 71.14,37.73 ; 75.35,55.45 GND#3.1 ; GND#3.1 76.55,54.24 ; GND#3.1 77.76,55.45 ; GND#3.1 76.55,56.65 ; D1.2 102.46,33.47 ; U2.G9 v2(56.82,48.67) ; 35.95,38.17 R69.1 36.36,37.72 ; U2.E1 v2(58.42,55.87) ; U4.D2 v2(57.93,38.55) ; v1(6.68,24.71) 6.28,24.32 D9.1 ; U5.D12 v2(32.34,27.28) ; U4.C15 v2(58.33,27.24) ; U4.E9 v2(57.13,32.15) ; U5.A12 v2(34.74,27.28) ; R75.2 102.13,13.97 ; R75.2 101.57,14.53 ; R75.2 101.01,13.97 ; U3.7 U3.8 ; U3.7 87.06,20.25 ; U3.8 88.72,19.6 v2(88.76,19.56) ; U3.8 87.06,19.6 ; 66.65,5.38 P1.7 ; 50.42,56.18 v2(50.42,55.87) U2.P1 ; U2.E8 v2(58.42,49.47) ; C33.2 31.21,17.09 v1(30.96,16.84) ; C81.2 43.19,56.58 ; U5.H9 v2(29.15,30.48) ; 38.8,38.17 R104.1 38.39,37.72 ; U4.G3 v2(55.53,37.75) ; 29.55,27.17 29.6,27.17 ; 29.6,27.17 29.54,27.23 U5.G12 ; C13.2 90.07,25.21 ; C13.2 88.95,25.21 ; C13.2 89.51,25.77 ; U4.B8 v2(58.73,33.75) ; 37.37,26.52 C193.1 37.37,27.13 ; U5.H1 v2(28.35,36.88) U5.J1 ; U5.C2 v2(33.14,36.08) U5.B2 ; U2.D8 v2(58.42,50.27) ; U6.22 90.3,43.52 ; U6.22 89.6,43.93 ; U6.22 88.94,43.52 88.8,43.66 ; U5.G1 v2(29.14,36.88) ; U2.M9 52.42,49.07 v2(52.02,48.67) ; U2.B9 v2(60.02,49.47) ; 38.15,36.29 C206.2 38.61,36.7 ; U5.B1 v2(33.14,36.88) U5.C1 ; D10.1 27.13,20.65 ; U4.L11 v2(51.53,30.55) ; 20.78,25.82 C129.1 20.32,26.22 ; U5.M6 v2(25.14,32.88) U5.M5 ; D7.1 22.23,10.84 ; 89.6,44.61 U6.19 ; U6.19 90.3,45.02 ; U2.G1 v2(56.82,55.87) ; 19.3,10.44 C202.2 ; GND#2.1 95.79,6.8 ; GND#2.1 93.38,6.8 ; GND#2.1 94.59,5.6 ; GND#2.1 94.59,8.01 ; U4.E8 56.73,33.35 v2(56.33,33.75) U4.E7 ; 97.89,39.44 C183.2 98.69,38.59 ; U4.H10 v2(54.73,31.35) ; U2.D1 v2(59.22,55.87) ; U5.H10 v2(29.15,29.68) ; U5.F11 v2(30.74,28.08) ; U5.K12 v2(26.74,27.28) ; U2.E2 v2(58.42,55.07) ; 50.42,48.23 v2(50.42,48.67) U2.P9 ; U4.K7 v2(53.13,34.55) ; U5.F7 v2(30.74,31.28) ; U4.K10 v2(52.33,31.35) ; 20.32,34.33 C194.1 20.78,34.73 ; U4.H6 v2(53.93,35.35) U4.J5 ; U2.T9 v2(48.82,48.67) 48.82,48.51 ; v1(11.16,32.71) 11.09,32.64 ; v1(12.06,13.48) 13.1,13.48 U17.8 14.09,13.44 ; 97.08,42.5 R61.1 ; 15.49,6.51 Q3.2 ; Q3.2 16.26,5.56 ; Q3.2 17.02,6.51 ; Q3.2 16.26,7.46 ; CLK_OUT.3 6.25,7.74 ; U2.F9 v2(56.82,49.47) ; U4.F10 v2(56.33,31.35) ; U5.B12 v2(33.94,27.28) ; 52.02,56.44 v2(52.02,55.87) U2.M1 ; U5.F3 v2(30.74,35.28) ; 39.6,57.52 C62.1 ; C164.2 82.27,26.11 v1(82.52,26.36) ; C164.2 81.57,26.57 ; C164.2 81.57,25.65 ; U2.J8 v2(55.22,49.47) ; U5.L3 v2(25.95,35.28) ; 107.25,23.03 S1.3 ; S1.3 108.03,23.98 ; S1.3 107.25,24.93 ; U4.A11 v2(60.53,30.95) ; 53.57,43.05 C57.2 54.13,43.6 ; U4.G5 v2(55.53,36.15) ; U2.A9 v2(61.62,48.67) ; U4.G13 v2(55.53,28.95) ; U4.M8 v2(50.73,33.75) ; 11.83,10.34 C201.2 11.37,9.93 ; U4.C5 v2(58.73,35.35) ; U2.J2 v2(55.22,55.07) ; D4.1 6.32,48.06 v1(6.23,48.15) ; D3.1 27.23,48.84 ; U13.B3 v2(73.62,46.29) ; 48.29,14 U12.3 ; U5.H2 v2(28.35,36.08) U5.J2 ; U5.A5 v2(34.85,33.28) ; T2.5 37.23,42.12 arc(37.2,42.32) 37.08,42.49 ; 6.9,10.75 D8.1 ; U5.D1 v2(32.34,36.88) ; U5.C4 v2(33.14,34.48) ; U4.P12 v2(49.13,29.75) ; U5.G10 v2(29.95,29.68) ; U4.R9 v2(48.25,32.55) ; v2(60.33,39.35) U4.A1 ; U4.K14 v2(53.13,28.94) ; U5.A4 v2(34.85,34.08) ; U4.E5 v2(57.13,36.15) ; U2.G8 v2(56.82,50.27)
  TOP w0.394: C18.2 v1(41.5,17.47) ; C16.2 40.23,17.22 v1(40.49,17.47) ; C25.2 30.58,12.27 v1(30.2,12.65)
  TOP w0.406: v2(51.73,42.95) 52.23,42.95 C58.2 ; C57.2 53.93,42.85 v2(53.53,42.85) ; v1(103.52,33.13) 103.76,33.37 P2.5
  TOP w0.508: 40.54,25.58 40.31,25.8 T3.5 ; T1.2 19.33,39.36 19.71,38.98 v1(19.71,38.81) ; 67.47,36.35 Y2.2 68.27,37.1 ; v1(44.33,52.85) C79.2 44.3,54.26 v1(44.3,55.34) 44.25,55.39 C81.2 ; C143.1 v1(96.86,44.54) ; 83.12,61.73 C185.2 ; C185.2 84.17,60.83 ; C185.2 85.23,61.73 ; 100.18,45.46 E10.1 ; E10.1 99.2,46.32 ; E10.1 101.15,46.32 ; 56.43,20.58 C68.2 ; C184.2 87.9,61.73 ; C184.2 86.84,60.83 ; C184.2 85.79,61.73
  TOP w0.635: C9.2 93.38,15 ; C9.2 92.68,14.36 ; C9.2 91.98,15 ; 35.85,14.3 C15.2 ; C15.2 36.49,13.6 ; C15.2 36.49,15 ; 87.39,56.25 C212.2 ; C212.2 87.39,57.95 ; C212.2 86.59,57.1 ; 49.38,14.01 v1(49.38,15.06) 49.38,16.11 ; C32.2 31.02,16.65 ; C32.2 31.02,15.25 ; C32.2 30.39,15.95 ; 38.01,17.21 C14.2 ; C14.2 38.71,17.84 ; C14.2 39.41,17.21 ; 92.77,51.93 C213.2 91.69,51.93 91.34,52.27 91.03,52.27 90.9,52.4 ; T5.5 16.83,30.27 v1(16.48,29.92) ; 86.59,59.13 C209.2 ; C209.2 87.39,58.28 ; C209.2 87.39,59.98 ; T1.5 19.89,39.04 ; C171.2 98.91,43.83 ; 89.09,62.43 U8.PAD 93.99,62.43 ; 30.39,10.36 C22.2 31.02,9.66 ; C173.2 49.57,18.04 ; C173.2 48.93,17.35 ; C173.2 49.57,16.65 ; C172.2 100.18,43.83 ; C151.2 85.66,55.14
  TOP w0.762: 84.14,19.7 C21.2 ; C21.2 86.24,19.7 ; C21.2 85.19,20.6 ; 88.17,39.7 C135.2 ; C135.2 88.81,39 ; C135.2 88.81,40.4 ; 87.92,50.62 C138.2 ; C138.2 88.56,51.32 ; C138.2 88.56,49.92 ; 65.63,56.3 C100.2 ; C100.2 65.63,58.41 ; C100.2 64.37,57.35 ; C100.2 66.89,57.35 ; 42.61,57.48 U14.PAD 40.6,57.48 ; C83.2 38.95,52.92 ; C83.2 37.25,52.92 ; C83.2 v1(38.1,51.74) ; 36.02,52.12 C82.2 ; C82.2 35.16,52.92 ; C82.2 36.87,52.92 ; C136.2 88.56,49.54 ; C136.2 88.56,48.14 ; C136.2 87.92,48.84 ; 103.35,29.66 R55.2 ; R55.2 104.02,30.57 ; R55.2 104.02,28.76 ; C54.2 61.27,43.06 ; C54.2 60.21,41.81 ; C54.2 60.21,44.32 ; C64.2 61.9,20.75 ; C64.2 61.9,18.64 ; C64.2 63.16,19.7 ; C64.2 60.64,19.7 ; C19.2 78.62,19.7 ; C19.2 76.52,19.7 ; C19.2 77.57,20.6 ; C17.2 82.65,20.6 ; C17.2 83.7,19.7 ; C17.2 81.6,19.7 ; C20.2 80.11,20.6 ; C20.2 81.16,19.7 ; C20.2 79.06,19.7 ; C71.2 59.9,19.76 ; C71.2 58.65,20.81 ; C71.2 57.39,19.76 ; C71.2 58.65,18.7 ; 88.17,37.92 C137.2 ; C137.2 88.81,38.62 ; C137.2 88.81,37.22
  TOP w1.016: 86.66,50.75 C148.2 85.76,51.8 ; 85.76,52.11 C145.2 ; C145.2 86.66,53.16 ; C145.2 85.76,54.21 ; C11.2 96.02,14.74 ; C11.2 94.97,13.84 ; C11.2 93.91,14.74 ; 87.73,37.67 C146.2
  TOP w1.27: 86.55,34.49 C150.2 ; C150.2 88.66,34.49 ; C150.2 87.6,33.23 ; C150.2 87.6,35.75 ; C149.2 87.6,32.7 ; C149.2 86.55,31.44 ; C149.2 88.66,31.44 ; C149.2 87.6,30.18
  L5_SIG w0.305: GND#2.1 94.59,8.01 ; GND#2.1 95.79,6.8 ; GND#2.1 94.59,5.6 ; GND#2.1 93.38,6.8 ; 76.55,54.24 GND#3.1 ; GND#3.1 76.55,56.65 ; GND#3.1 77.76,55.45 ; GND#3.1 75.35,55.45 ; GND.1 35.34,65.22 ; GND.1 33.18,65.22 ; GND.1 34.26,64.14 ; GND.1 34.26,66.3 ; GND#4.1 59.66,11.38 ; GND#4.1 60.43,10.61 ; GND#4.1 59.66,9.85 ; GND#4.1 58.9,10.61
  L6_SIG w0.305: GND#3.1 76.55,56.65 ; GND#3.1 77.76,55.45 ; GND#3.1 75.35,55.45 ; GND#3.1 76.55,54.24 ; 68.71,6.17 P1.9 67.92,5.38 ; 66.65,5.38 P1.7 ; GND#4.1 60.43,10.61 ; GND#4.1 59.66,9.85 ; GND#4.1 59.66,11.38 ; GND.1 34.26,66.3 ; GND.1 34.26,64.14 ; GND.1 33.18,65.22
  BOTTOM w0.254: 19.66,51.51 19.89,51.74 C4.2 ; C4.2 18.55,52.36 v1(18.51,52.4) ; C4.2 19.89,53.06 19.78,53.16 ; v1(19.53,55.19) 19.57,55.16 C6.2 ; v1(19.53,53.92) 19.57,53.89 C5.2
  BOTTOM w0.305: C48.2 73.11,46.73 ; C48.2 73.59,46.33 v2(73.62,46.29) ; C48.2 72.65,46.33 ; 72.24,33.06 C47.2 71.27,32.65 R15.2 ; 92.94,45.63 C139.1 ; C139.1 92.38,46.19 ; C139.1 93.5,46.19 ; 61.09,31.85 C69.2 60.53,31.29 ; 93.39,64.56 R72.2 ; R72.2 94.51,64.56 ; R72.2 93.95,65.1 ; 62.23,48.35 C97.2 61.7,48.75 v2(61.62,48.67) ; 56.07,27.73 C161.2 56.53,27.32 ; 63.55,40.51 R66.1 ; R66.1 64.08,41.07 ; R66.1 64.08,39.95 ; 56.22,49.95 C92.2 ; C92.2 56.68,50.35 ; C92.2 55.76,50.35 ; 34.26,64.14 GND.1 ; GND.1 35.34,65.22 ; GND.1 34.26,66.3 ; GND.1 33.18,65.22 ; 25.13,50.91 C2.2 24.67,50.51 ; C155.2 19.18,31.12 ; C155.2 18.38,30.27 ; C155.2 19.18,29.42 ; 20.32,15.03 C198.2 21.17,14.23 ; 55.32,53.91 C89.2 55.22,54.57 v2(55.22,55.07) ; C30.2 32.45,25.78 ; C30.2 31.89,25.22 ; C30.2 31.89,26.34 ; C28.2 30.85,38.14 ; 20.13,55.16 C6.2 ; v2(48.82,55.87) 48.9,55.95 C96.2 ; 28.44,37.02 C34.2 ; C34.2 28.44,38.14 ; C34.2 29,37.58 ; 93.74,46.17 R63.2 ; R63.2 94.14,46.63 ; R63.2 94.14,45.84 93.76,45.46 93.3,45.46 v2(93.27,45.49) ; 94.59,5.6 GND#2.1 ; GND#2.1 94.59,8.01 ; GND#2.1 93.38,6.8 ; GND#2.1 95.79,6.8 ; v2(58.42,55.87) 58.34,55.95 C95.2 58.75,56.48 ; C189.2 70.27,59.97 ; C189.2 70.67,59.51 ; C189.2 70.27,59.05 ; 58.8,56.48 C94.2 59.21,55.88 v2(59.22,55.87) ; 45.63,29.79 C108.2 ; C108.2 v2(45.63,30.94) ; C108.2 45.07,30.35 ; 20.12,53.89 C5.2 ; C59.2 53.09,39.55 ; C59.2 52.53,40.11 ; C59.2 51.97,39.55 ; 59.77,60.56 U10.3 ; U10.3 59.77,62.01 ; U10.3 59.36,61.29 ; 25.33,12.68 C195.2 26.19,13.49 ; 95.57,41.73 C147.1 96.12,41.17 ; 90.9,22.01 R3.1 ; R3.1 91.46,22.57 ; R3.1 90.35,22.57 ; C114.2 47.43,28.11 ; C114.2 47.43,26.99 ; C114.2 47.52,27.64 v2(47.52,28.14) 47.52,28.66 C112.2 47.43,29.34 47.43,29.34 ; R78.1 91.16,65.1 ; R78.1 90.6,64.56 ; R78.1 91.72,64.56 ; 57.92,39.04 C99.1 58.38,39.45 ; v2(54.33,26.55) 54.35,26.53 C119.2 ; 54.63,31.39 C74.2 ; C74.2 54.63,32.51 ; C74.2 54.07,31.95 ; 59.53,26.69 C111.2 ; C111.2 58.97,27.25 ; C111.2 60.09,27.25 ; 62.02,59.79 R93.2 ; R93.2 62.58,59.26 ; R93.2 63.14,59.79 ; R40.2 54.39,41.25 ; R40.2 53.27,41.25 ; R40.2 53.63,41.05 v2(53.13,41.05) ; v2(33.14,34.48) 33.14,34.66 C42.2 ; 49.22,29.89 C116.2 48.67,30.45 ; 45.63,31.39 C78.2 ; C78.2 45.07,31.95 ; C78.2 v2(45.63,32.56) C90.2 ; v1(46.84,57.48) 46.45,57.48 46.21,57.24 R42.2 ; 33.12,36.81 C208.2 32.66,37.22 ; 49.16,48.87 C86.2 ; C86.2 49.52,48.67 v2(48.82,48.67) ; C86.2 49.92,48.67 v2(50.42,48.67) ; 34.51,34.38 C37.2 33.95,33.82 ; 71.85,59.35 C196.1 ; C196.1 72.44,59.9 ; C196.1 71.27,59.9 ; 52.72,32.61 C72.2 53.28,32.05 ; 73.07,50.1 R116.2 74.19,50.1 ; GND#4.1 59.66,11.38 ; GND#4.1 58.9,10.61 ; GND#4.1 59.66,9.85 ; GND#4.1 60.43,10.61 ; C55.2 56.29,40.95 ; C55.2 55.73,41.51 ; C55.2 55.17,40.95 ; 39.55,28.72 C167.2 ; C167.2 40.71,28.83 ; C167.2 40.67,30 ; 55.03,24.09 C105.2 55.59,24.65 ; C91.2 56.28,49.39 ; C91.2 55.3,49.39 v2(55.22,49.47) ; C91.2 55.82,49.8 ; 7.11,5.45 Q2.2 ; Q2.2 7.11,7.36 ; Q2.2 6.35,6.41 ; Q2.2 7.87,6.41 ; 60.17,49.56 C87.2 60.73,50.12 ; C102.2 52.5,49.15 v2(52.02,48.67) ; 63.46,60.57 U9.13 64.24,60.13 ; v2(34.85,32.48) 34.75,32.37 C27.2 ; 70.58,37.97 C174.2 71.14,37.41 ; 57.79,32.85 C75.2 57.23,32.29 ; C90.2 45.63,33.71 ; C90.2 45.07,33.15 ; 68.71,6.17 P1.9 67.92,5.38 ; 93.9,43.9 R54.2 94.46,43.34 ; 15.1,15.52 C124.2 14.69,15.06 ; 34.61,26.19 C127.2 ; C127.2 35.17,26.74 ; C127.2 35.16,25.63 ; v2(33.14,29.68) 33.23,29.6 C40.2 33.23,28.96 v2(33.14,28.88) ; v2(33.14,30.48) 33.23,30.56 33.23,31.2 v2(33.14,31.28) ; 42.86,57.6 C101.2 ; C101.2 43.42,57.05 ; C101.2 43.42,58.16 ; v1(88.11,25.09) R2.1 ; R2.1 87.55,24.32 ; R2.1 88.67,24.32 ; v1(66.14,61.54) v1(65.5,62.18) ; v1(66.14,61.54) v1(66.77,62.18) ; v1(66.14,61.54) v1(65.5,60.91) ; v1(66.14,61.54) v1(66.77,60.91) ; 51.53,27.49 C110.2 ; 77.84,27.07 R77.2 77.84,28.19 ; 28.37,35.88 C39.2 28.16,36.08 v2(28.35,36.08) ; 59.13,24.09 C113.2 ; C113.2 v2(59.83,24.65) C107.2 ; C113.2 58.57,24.65 ; 56.35,56.34 C63.1 56.76,55.88 ; 54.17,33.66 C70.2 54.73,33.1 ; C44.2 29.87,27.68 ; C44.2 29.46,27.33 v2(29.65,27.15) 29.64,27.14 C38.2 29.64,25.91 ; C44.2 29.46,28.14 ; 60.43,30.85 C162.2 60.05,30.39 ; 60.43,30.85 60.46,30.85 ; 60.43,30.85 v2(60.53,30.95) ; 25.62,35.4 25.62,35.38 ; 25.62,35.4 25.83,35.4 v2(25.95,35.28) 26.01,35.21 C41.2 ; 25.62,35.4 C24.2 25.22,35.88 ; 68.73,57.41 C187.2 69.19,57.01 ; C197.1 72.44,63.31 ; C197.1 71.85,63.86 ; C197.1 71.27,63.31 ; 67.85,57.67 C215.2 68.49,56.97 ; C142.1 97.67,43.76 ; 25.37,30.72 C207.1 ; C207.1 24.92,31.13 ; C207.1 25.83,31.13 ; 78.13,23.14 C165.2 ; C165.2 78.98,22.34 ; C165.2 79.83,23.14 ; R15.2 71.22,33.26 ; R15.2 70.66,32.7 ; R119.2 68.82,48.77 ; 60.53,24.09 C107.2 ; C107.2 61.09,24.65 ; 33.93,32.43 C203.2 33.47,32.02 ; 59.44,34.6 C178.2 58.88,35.16 ; R65.1 93.95,42.91 ; R65.1 94.51,42.35 ; R65.1 93.39,42.35 ; 53.63,24.09 C109.2 ; 92,64.56 R73.2 ; R73.2 92.56,65.1 ; R73.2 93.12,64.56 ; v1(77.57,31.05) C140.2 76.81,31.61 ; C23.2 32.05,36.58 v2(32.34,36.88) 32.34,36.89 ; 68.82,46.63 R120.2 ; 29.24,38.66 C126.1 ; C126.1 29.74,39.19 ; C126.1 30.25,38.66 ; 26.01,59.47 26.01,59.07 26.01,59.51 ; 35.86,32.93 C31.2 35.3,32.37 ; 50.17,27.83 C118.2 50.63,27.42 ; C190.2 62.15,65.16 ; 56.53,24.42 C117.2 ; C117.2 56.08,24.83 ; C117.2 56.96,24.83 v2(57.14,24.65) ; 76.55,54.24 GND#3.1 ; GND#3.1 77.76,55.45 ; GND#3.1 76.55,56.65 ; GND#3.1 75.35,55.45 ; 75.79,27.09 C154.2 75.23,27.65 ; 48.67,33.03 C120.2 49.13,32.63 ; 25.94,38.43 C29.2 25.38,37.87 ; v1(94.59,39.7) 94.52,39.76 C7.1 93.83,39.35 ; R90.2 83.81,43.93 ; R90.2 83.25,43.39 ; R90.2 84.37,43.39 ; C88.2 60.82,56.49 v2(60.82,55.87) ; R92.2 70.89,57 ; R92.2 70.33,56.46 ; R92.2 69.77,57 ; 47.52,35.13 C61.2 ; U11.3 22.18,12.69 ; C191.2 24.28,29.96 ; v2(25.63,54.3) 25.63,54.25 25.31,53.94 U1.6 ; 54.02,36.71 C73.2 54.02,35.59 ; C192.2 23.67,29.81 ; C192.2 22.65,29.81 ; C192.2 23.16,30.35 ; R121.2 72.16,43.52 ; 26.72,14.2 C123.2 ; 66.65,5.38 P1.7 ; 51.33,24.09 C106.2 ; C188.2 67.5,58.11 ; 40.33,53.81 C80.2 39.88,54.21 ; 23.92,32.85 C36.2 ; C36.2 24.48,32.29 ; C36.2 24.51,32.88 v2(25.14,32.88) ; C35.2 35.75,30.43 ; 64.02,64.97 C186.2 64.43,64.51 ; 35.25,26.95 C128.2 ; 57.74,24.09 C115.2 58.3,24.65 ; C125.1 v2(30.74,35.28) ; C26.2 31.77,26.68 ; 61.65,34.45 C53.2 61.25,34.91 ; C122.2 15.59,9.28 ; 52.26,44.87 R165.2 v1(53.72,44.87) ; U9.3 66.46,64.22 ; 61.25,34.99 C52.2 ; 76.81,27.09 C168.2 ; 47.1,34.8 C51.2 46.54,34.24 ; 52.53,24.09 C67.2
  BOTTOM w0.406: v2(53.13,28.94) 53.83,29.65 C66.2 ; C50.2 63.03,30.95 v2(63.03,30.95) C159.2 v2(63.03,29.74) C160.2 ; v2(51.93,39.45) 52.43,39.45 C59.2 ; v2(34.74,27.28) 34.82,27.35 C128.2 ; C115.2 v2(57.14,24.65) ; C106.2 v2(51.93,24.65) C67.2 ; C72.2 52.63,31.95 52.63,31.65 v2(52.33,31.35) ; C28.2 30.74,37.47 v2(30.74,36.88) ; C109.2 v2(54.34,24.65) C105.2
  BOTTOM w0.508: v1(68.04,48.21) R119.2 ; C35.2 36.45,29.87 ; C34.2 28.35,37.49 v2(28.35,36.88) ; C121.2 17.22,10.77 ; C121.2 16.37,9.97 ; C121.2 18.07,9.97 ; v1(71.6,42.75) R121.2 ; 23.26,12.69 U11.PAD 23.26,10.58 ; C142.1 97.12,44.28 v1(96.86,44.54) ; v1(68.04,47.19) R120.2 ; v1(73.63,50.87) R116.2 ; v1(70.58,39.57) 70.27,39.25 R91.2 ; C29.2 v1(26.64,37.87)
  BOTTOM w0.635: C153.2 86.27,33.28 ; C153.2 86.27,31.89 ; C153.2 86.9,32.59 ; 71.63,39.86 E6.1 ; E6.1 71.63,41.82 ; E6.1 72.48,40.84 ; C4.2 19.89,53.06 ; C4.2 19.89,51.66 ; C4.2 19.25,52.37 ; 22.02,60.42 C3.2 ; C3.2 23.72,60.42 ; C3.2 22.88,61.22 ; C85.2 65.69,35.95 v1(66.94,35.95) ; C152.2 86.9,34.11 ; C152.2 86.27,34.81 ; C152.2 86.27,33.41 ; 31.97,22.68 arc(31.97,22.68) 31.98,22.68
  BOTTOM w0.762: 68.04,31.32 69.1,31.32 ; 68.04,31.32 68.04,30.06 ; 68.04,31.32 68.04,32.57 ; 68.04,27.89 68.04,29.14 ; 68.04,27.89 68.04,26.63 ; 68.04,27.89 69.1,27.89 ; C76.2 41.22,37.01 ; C76.2 41.22,34.49 ; C76.2 42.28,35.75 ; C76.2 40.17,35.75 ; C77.2 41.71,32.47 ; C77.2 41.71,30.37 ; C77.2 40.81,31.42 ; C104.2 46.62,23 ; C104.2 44.51,23 ; C104.2 45.57,22.09 ; 61.38,25.49 C103.2 ; C103.2 62.43,24.59 ; C103.2 63.49,25.49 ; 66.69,35.9 C85.2 64.58,35.9 ; 12.1,9.67 Y3.2 12.1,11.57 ; 48.49,22.09 C65.2 ; C65.2 47.43,23 ; C65.2 49.54,23
  vias: v1(1.6,24.71) v1(1.57,21.18) v1(2.42,48.15) v1(2.59,44.62) v1(2.59,21.18) v1(2.87,24.71) v1(3.15,58.24) v1(3.15,53.16) v1(3.15,39.19) v1(3.15,34.11) v1(3.15,16.33) v1(3.15,11.25) v1(3.69,48.15) v1(3.86,44.62) v1(3.86,21.18) v1(4.14,24.71) v1(4.96,48.15) v1(5.03,8.51) v1(5.03,7.74) v1(5.13,44.62) v1(5.13,21.18) v1(5.18,10.61) v1(5.41,24.71) v1(5.69,55.7) v1(5.69,36.65) v1(5.69,31.57) v1(5.69,13.79) v1(5.74,9.57) v1(6.25,14.81) v1(6.4,44.62) v1(6.4,21.18) v1(6.4,10.74) v1(6.55,12.88) v1(6.91,4.85) v1(7.26,21.21) v1(7.52,48.18) v1(7.47,24.71) v1(7.57,44.68) v1(8.13,4.85) v1(8.23,64.46) v1(8.23,58.24) v1(8.23,53.16) v1(8.23,34.11) v1(8.23,21.28) v1(8.28,40.05) v1(8.33,25.22) v1(8.74,48.21) v1(8.74,44.52) v1(8.74,28.57) v1(8.74,27.4) v1(8.74,26.34) v1(8.89,29.79) v1(8.94,10.18) v1(9.09,14.09) v1(9.19,21.26) v1(9.24,4.9) v1(9.45,30.81) v1(9.75,15.97) v1(10.03,47.99) v1(10.11,44.12) v1(10.11,21.42) v1(10.13,31.96) v1(10.56,17.35) v1(10.77,55.7) v1(10.77,50.62) v1(10.77,41.73) v1(10.77,36.65) v1(10.77,12.93) v1(10.92,22.48) v1(11.22,47.55) v1(11.21,43.48) v1(11.38,9.47) v1(11.73,23.39) v1(11.78,21.54) v1(11.94,24.71) v1(12.09,27.4) v1(12.09,26.13) v1(12.21,28.78) v1(12.14,15.16) v1(12.32,46.92) v1(12.31,42.85) v1(12.44,33.14) v1(12.5,22.17) v1(12.67,65.1) v1(12.75,18.41) v1(12.95,9.52) v1(13.07,29.71) v1(13.31,39.19) v1(13.42,46.28) v1(13.41,42.21) v1(13.58,29) v1(13.92,33.25) v1(14.2,28.01) v1(14.52,45.65) v1(14.51,41.58) v1(14.7,21.23) v1(14.88,33.3) v1(15.29,19.48) v1(15.47,28.01) v1(15.62,45.01) v1(15.61,40.94) v1(15.85,50.62) v1(15.85,12.52) v1(16.15,33.3) v1(16.2,11.96) v1(16.36,19.63) v1(16.36,4.39) v1(16.46,29) v1(16.71,40.31) v1(16.76,44.37) v1(16.75,39.38) v1(16.74,28.01) v1(16.86,38.3) v1(16.99,65.73) v1(17.12,20.39) v1(17.42,33.3) v1(17.63,27.51) v1(17.63,15.72) v1(17.63,5.79) v1(17.82,43.74) v1(17.88,21.16) v1(18.01,37.67) v1(18.26,18.62) v1(18.51,9.98) v1(18.69,33.3) v1(18.92,43.11) v1(18.9,27.51) v1(18.9,7.44) v1(19.17,37.99) v1(19.15,36.78) v1(19.4,51) v1(19.78,35.89) v1(19.81,9.22) v1(19.91,5.92) v1(19.96,33.3) v1(20.17,25.6) v1(20.52,16.58) v1(20.67,35.38) v1(20.67,23.44) v1(20.93,3.63) v1(21.18,60.65) v1(21.18,41.73) v1(21.44,19.25) v1(21.44,5.86) v1(21.69,45.79) v1(21.82,35.25) v1(21.89,22.43) v1(21.94,66.37) v1(22.1,13.18) v1(22.45,40.97) v1(22.58,47.7) v1(22.71,9.22) v1(22.96,61.92) v1(22.96,5.92) v1(23.32,50.06) v1(23.47,40.08) v1(23.47,13.28) v1(23.72,35.38) v1(23.77,24.15) v1(23.98,44.9) v1(23.98,16.33) v1(24.18,7.49) v1(24.48,60.53) v1(24.61,49.98) v1(24.86,9.98) v1(24.99,38.05) v1(25.25,38.94) v1(25.25,14.3) v1(25.37,49.98) v1(25.4,22.53) v1(25.8,3.93) v1(26.01,59.89) v1(25.96,45.49) v1(26.13,13.92) v1(26.26,21.66) v1(26.47,16.99) v1(27.02,20.9) v1(27.53,66.88) v1(27.79,49.48) v1(29.67,45.79) v1(30.2,16.84) v1(30.2,15.95) v1(30.2,11.5) v1(30.2,10.74) v1(30.2,9.98) v1(30.33,49.1) v1(30.99,14.3) v1(31.09,60.78) v1(31.09,15.06) v1(31.09,7.13) v1(31.34,49.1) v1(32.23,49.1) v1(32.51,45.74) v1(32.74,7.19) v1(33.25,49.1) v1(33.48,45.74) v1(34.26,49.1) v1(34.39,45.74) v1(34.52,7.19) v1(34.64,52.52) v1(35.28,49.1) v1(35.28,45.74) v1(35.66,14.3) v1(35.79,23.19) v1(35.91,43.25) v1(36.17,7.19) v1(36.29,49.1) v1(36.68,15.31) v1(37.23,43.25) v1(37.44,48.97) v1(37.82,17.47) v1(38.58,37.16) v1(39.47,37.36) v1(39.6,17.47) v1(39.98,43) v1(39.98,40.51) v1(40.23,57.22) v1(42.64,49.86) v1(43.28,38.43) v1(43.41,51.25) v1(43.66,7.19) v1(43.91,38.81) v1(45.69,13.79) v1(45.83,36.01) v1(46.58,13.79) v1(47.22,60.78) v1(47.34,67.13) v1(47.47,63.83) v1(47.47,13.79) v1(47.6,7.44) v1(48.82,13.23) v1(49.38,16.33) v1(49.38,13.79) v1(49.82,11.73) v1(55.22,9.98) v1(55.34,19.63) v1(56.11,20.27) v1(56.74,19.63) v1(57.12,20.27) v1(57.25,1.34) v1(58.65,61.29) v1(58.77,12.14) v1(59.79,60.02) v1(60.25,20.2) v1(60.25,19.19) v1(60.55,1.34) v1(61.06,10.11) v1(62.03,24.44) v1(62.83,24.44) v1(63.42,20.2) v1(63.42,19.19) v1(63.85,1.34) v1(63.98,59.64) v1(64.11,57.6) v1(64.36,56.21) v1(65.5,58.62) v1(66.65,48.08) v1(66.9,64.59) v1(67.28,1.47) v1(67.41,32.84) v1(67.41,29.54) v1(67.79,57.99) v1(67.92,50.62) v1(68.43,32.84) v1(68.43,29.54) v1(68.68,56.21) v1(69.19,56.59) v1(69.2,29.54) v1(69.44,32.84) v1(70.71,38.43) v1(71.47,64.08) v1(71.47,59.13) v1(71.6,39.57) v1(71.6,38.43) v1(71.98,1.72) v1(72.11,64.08) v1(72.14,33.53) v1(72.24,59.13) v1(73,7.44) v1(73.25,63.07) v1(73.25,4.77) v1(74.01,62.94) v1(74.14,10.74) v1(74.14,9.85) v1(74.27,61.67) v1(74.39,62.43) v1(75.54,46.56) v1(76.05,20.27) v1(76.05,19.12) v1(77.08,20.94) v1(78.85,19.92) v1(78.84,19.12) v1(79.07,48.82) v1(80.05,23.74) v1(80.11,21.03) v1(81.35,23.74) v1(81.38,20.27) v1(81.38,19.25) v1(82.65,21.03) v1(82.75,23.74) v1(83.54,60.53) v1(83.92,20.27) v1(83.92,19.25) v1(84.05,66.88) v1(84.17,27.51) v1(84.17,2.74) v1(84.68,60.53) v1(84.68,24.46) v1(84.85,21.04) v1(84.94,28.27) v1(85.95,25.73) v1(86.08,66.88) v1(86.08,59.64) v1(86.08,59) v1(86.08,57.48) v1(86.08,56.84) v1(86.21,60.53) v1(86.33,54.56) v1(86.59,44.52) v1(86.59,43.89) v1(86.59,36.4) v1(86.71,28.27) v1(86.71,26.24) v1(86.71,22.3) v1(86.71,21.28) v1(86.71,20.27) v1(86.71,19.25) v1(86.84,53.54) v1(86.84,52.52) v1(86.84,51.51) v1(86.84,50.62) v1(87.48,60.53) v1(87.48,32.97) v1(87.6,51.51) v1(87.6,50.62) v1(87.6,49.73) v1(87.6,48.46) v1(87.6,44.52) v1(87.6,43.89) v1(87.86,39.95) v1(87.86,39.19) v1(87.86,38.43) v1(87.86,37.54) v1(87.86,36.78) v1(88.24,32.97) v1(88.49,28.27) v1(88.62,51.51) v1(88.62,49.73) v1(88.62,44.52) v1(88.62,43.89) v1(88.75,37.03) v1(89,36.14) v1(89,35.25) v1(89,34.24) v1(89,33.22) v1(89,32.2) v1(89,31.06) v1(89.51,25.98) v1(90.14,52.27) v1(90.27,62.43) v1(90.27,25.22) v1(91.03,28.27) v1(91.03,26.24) v1(91.16,3.25) v1(91.41,13.92) v1(91.67,65.99) v1(91.79,62.43) v1(92.43,50.87) v1(92.43,50.24) v1(92.43,49.6) v1(92.81,52.27) v1(92.81,51.64) v1(92.81,28.27) v1(92.81,26.24) v1(92.94,50.62) v1(92.94,49.98) v1(92.94,49.35) v1(93.19,65.99) v1(93.32,62.43) v1(93.32,8.2) v1(93.52,13.99) v1(93.7,28.27) v1(94.33,32.59) v1(94.33,31.7) v1(94.33,30.93) v1(94.33,30.17) v1(94.33,29.41) v1(94.33,28.65) v1(94.33,26.11) v1(94.59,38.81) v1(94.59,23.95) v1(94.97,58.37) v1(95.48,63.95) v1(95.5,26.59) v1(95.86,8.07) v1(96.24,27.38) v1(96.49,16.58) v1(96.62,33.6) v1(96.62,32.84) v1(96.62,32.08) v1(96.62,31.32) v1(96.62,30.55) v1(96.62,29.79) v1(96.62,29.03) v1(96.62,28.27) v1(96.75,65.48) v1(96.75,62.68) v1(97.17,39.61) v1(97.17,38.97) v1(97.25,58.37) v1(97.23,40.61) v1(97.3,37.45) v1(97.3,36.81) v1(98.7,46.35) v1(98.69,45.7) v1(98.69,45.07) v1(99.16,13.79) v1(99.33,45.07) v1(99.67,23.95) v1(99.79,64.97) v1(99.92,56.59) v1(100.98,33.13) v1(100.98,32.5) v1(100.98,31.86) v1(100.98,31.23) v1(101.45,46.2) v1(101.45,45.54) v1(101.57,56.59) v1(101.62,33.13) v1(101.62,32.5) v1(101.62,31.86) v1(101.62,31.23) v1(101.98,20.52) v1(102.21,22.68) v1(102.21,15.06) v1(102.25,33.13) v1(102.25,32.5) v1(102.25,31.86) v1(102.25,31.23) v1(102.72,64.46) v1(102.89,33.13) v1(102.89,32.5) v1(102.89,31.86) v1(102.89,31.23) v1(103.1,56.59) v1(103.52,32.5) v1(103.52,31.86) v1(103.52,31.23) v1(103.48,6.17) v1(104.11,27.89) v1(105.51,58.37) v1(106.02,16.33) v1(106.19,45.07) v1(106.19,44.43) v1(106.65,62.68) v1(106.82,45.07) v1(106.82,44.43) v1(107.29,60.65) v1(107.29,58.37) v1(107.29,22.68) v1(107.8,28.9) v2(1.02,51.84) v2(1.02,50.82) v2(1.02,49.81) v2(1.02,43.08) v2(1.02,42.06) v2(1.02,41.04) v2(1.02,28.34) v2(1.02,27.33) v2(1.02,26.31) v2(1.02,19.58) v2(1.02,18.57) v2(1.02,17.55) v2(2.03,51.84) v2(2.03,50.82) v2(2.03,49.81) v2(2.03,43.08) v2(2.03,42.06) v2(2.03,41.04) v2(2.03,28.34) v2(2.03,27.33) v2(2.03,26.31) v2(2.03,19.58) v2(2.03,18.57) v2(2.03,17.55) v2(3.05,51.84) v2(3.05,50.82) v2(3.05,49.81) v2(3.05,43.08) v2(3.05,42.06) v2(3.05,41.04) v2(3.05,28.34) v2(3.05,27.33) v2(3.05,26.31) v2(3.05,19.58) v2(3.05,18.57) v2(3.05,17.55) v2(4.06,51.84) v2(4.06,50.82) v2(4.06,49.81) v2(4.06,43.08) v2(4.06,42.06) v2(4.06,41.04) v2(4.06,28.34) v2(4.06,27.33) v2(4.06,26.31) v2(4.06,19.58) v2(4.06,18.57) v2(4.06,17.55) v2(5.08,51.84) v2(5.08,50.82) v2(5.08,49.81) v2(5.08,43.08) v2(5.08,42.06) v2(5.08,41.04) v2(5.08,28.34) v2(5.08,27.33) v2(5.08,26.31) v2(5.08,19.58) v2(5.08,18.57) v2(5.08,17.55) v2(22.2,17.45) v2(24.36,55.57) v2(24.36,54.94) v2(24.36,54.3) v2(24.99,55.57) v2(24.99,54.94) v2(24.99,54.3) v2(25.63,55.57) v2(25.63,54.94) v2(29.82,25.42) v2(35.53,30.3) v2(38.1,32.99) v2(40.38,24.56) v2(40.44,12.7) v2(40.44,11.88) v2(40.44,11.07) v2(41.25,12.7) v2(41.25,11.07) v2(41.37,22.04) v2(42.01,24.97) v2(42.06,12.7) v2(42.06,11.88) v2(42.06,11.07) v2(42.26,29.92) v2(42.67,28.83) v2(42.9,27.89) v2(43.15,26.87) v2(43.15,25.85) v2(43.18,23.09) v2(44.3,23.19) v2(46.72,35.05) v2(46.96,23.19) v2(49.76,23.19) v2(56.43,40.85) v2(57.13,27.15) v2(60.02,51.87) v2(60.82,51.87) v2(60.93,44.45) v2(61.25,34.95) v2(61.62,43.06) v2(61.62,42.26) v2(75.33,26.95) v2(75.33,25.73) v2(75.33,24.51) v2(75.94,26.34) v2(75.94,25.12) v2(76.55,26.95) v2(76.55,25.73) v2(76.55,24.51) v2(77.16,26.34) v2(77.16,25.12) v2(77.77,26.95) v2(77.77,25.73) v2(77.77,24.51) v2(78.33,66.42) v2(80.41,62.51) v2(81.08,61.74) v2(88.76,21.59) v2(88.76,20.57) v2(89.78,21.59) v2(89.78,19.56) v2(90.8,21.59) v2(90.8,20.57) v2(90.8,19.56) v2(90.83,45.49) v2(90.83,44.27) v2(90.83,43.05) v2(91.44,44.88) v2(91.44,43.66) v2(92.05,45.49) v2(92.05,44.27) v2(92.05,43.05) v2(92.66,44.88) v2(92.66,43.66) v2(93.27,44.27) v2(93.27,43.05)
